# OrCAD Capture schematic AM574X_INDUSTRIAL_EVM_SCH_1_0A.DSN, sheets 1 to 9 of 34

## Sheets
1 Pg09: DDR3 Memory 2: size C; title: TITLE; rev: A; company: Texas Instruments; note: Proj PROC053 001 OPN# TMDSIDK574; note: Catalog Processors BU; note: Final
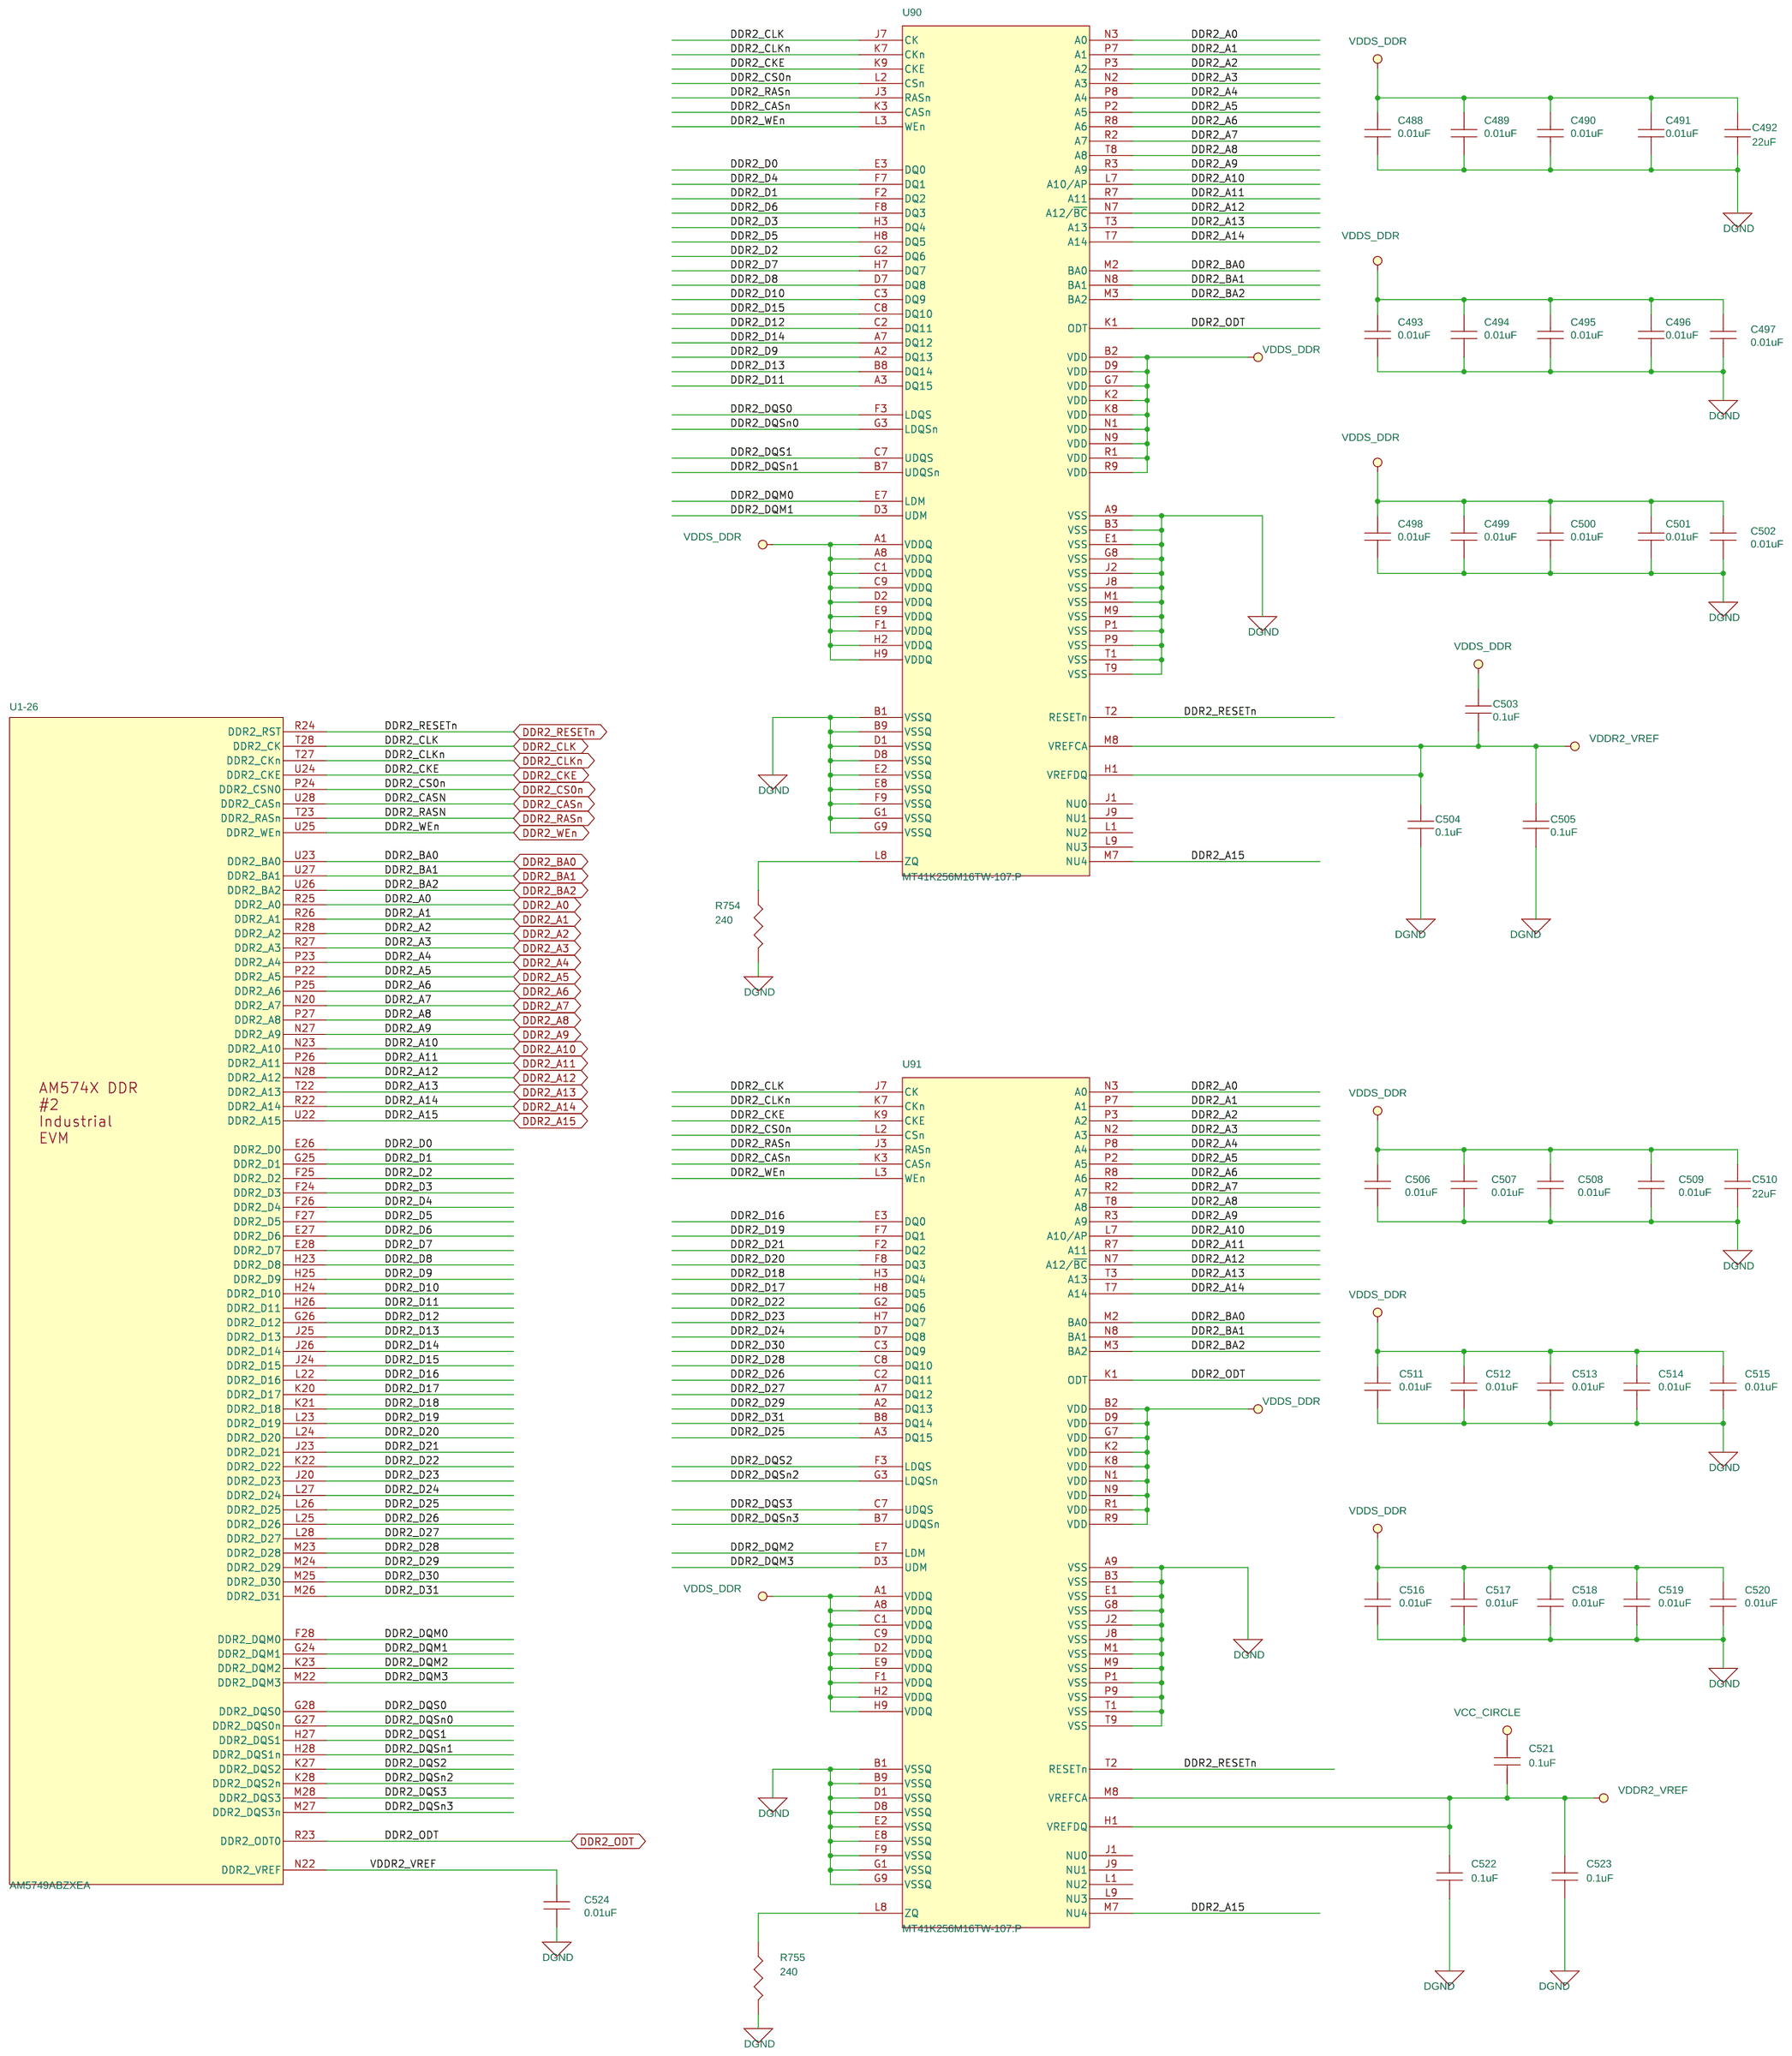
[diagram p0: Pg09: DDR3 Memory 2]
2 Pg24: USB JTAG: size C
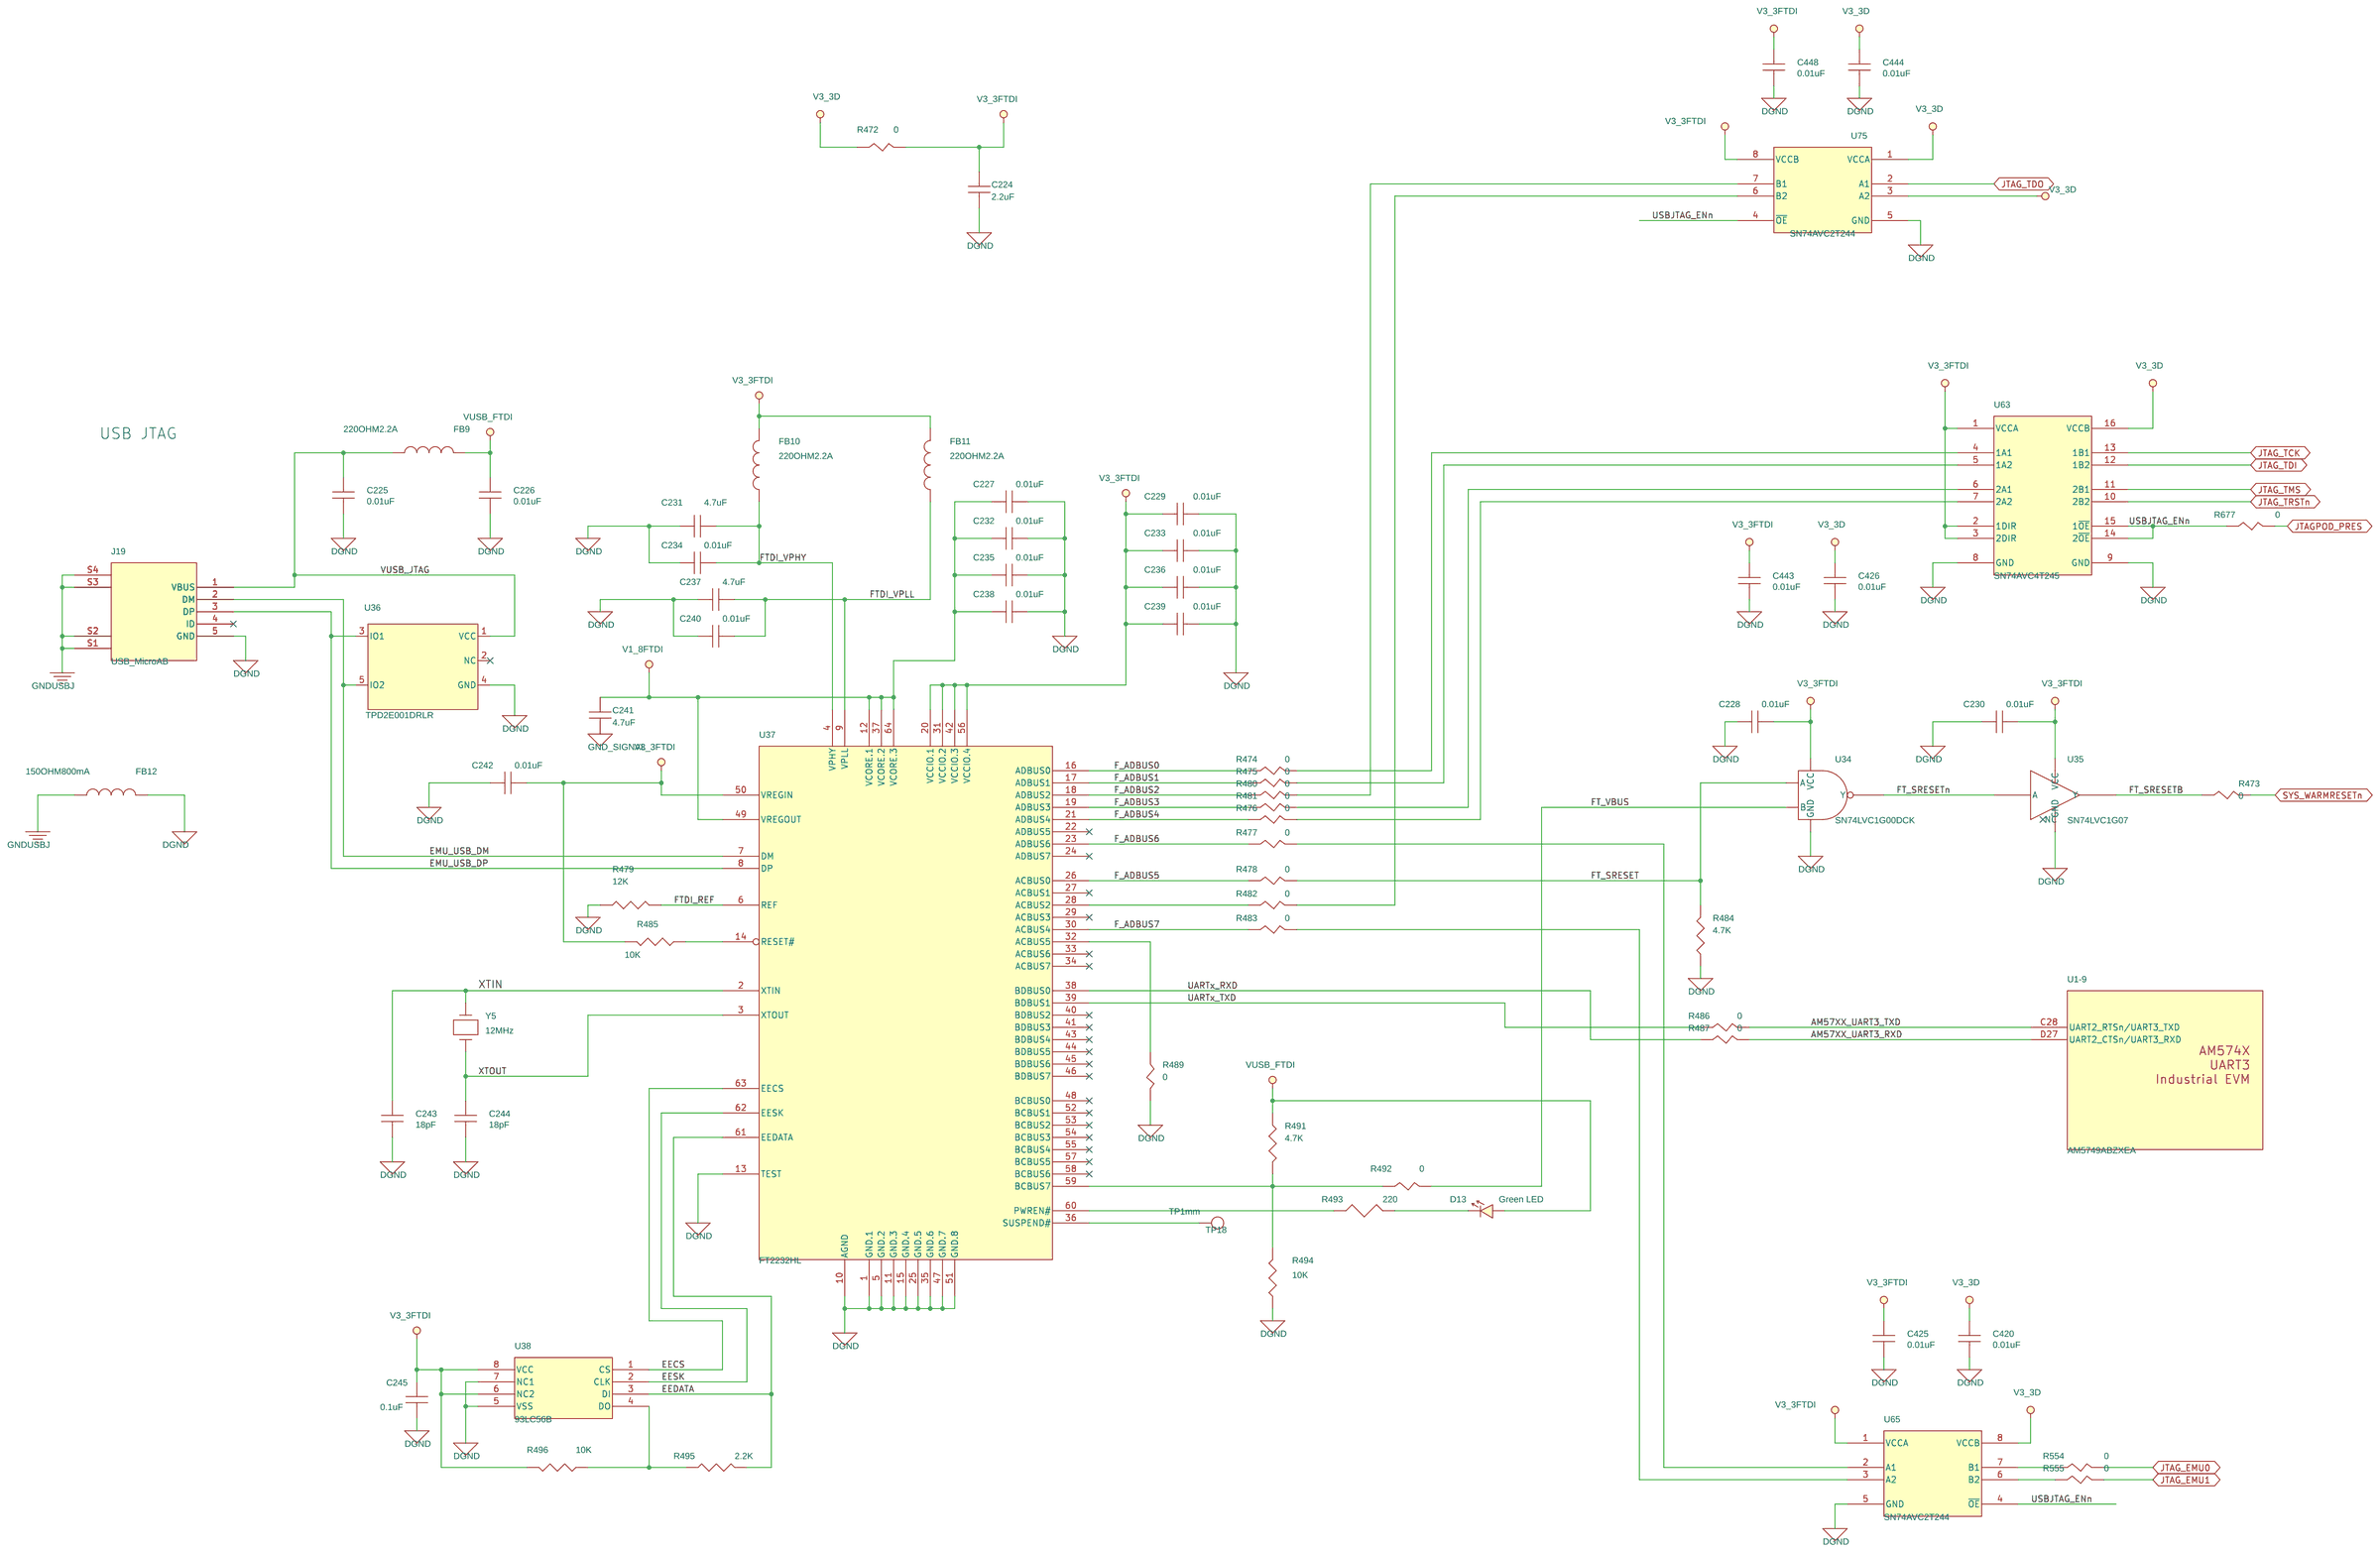
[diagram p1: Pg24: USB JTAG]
3 Pg30: RS-485: size C
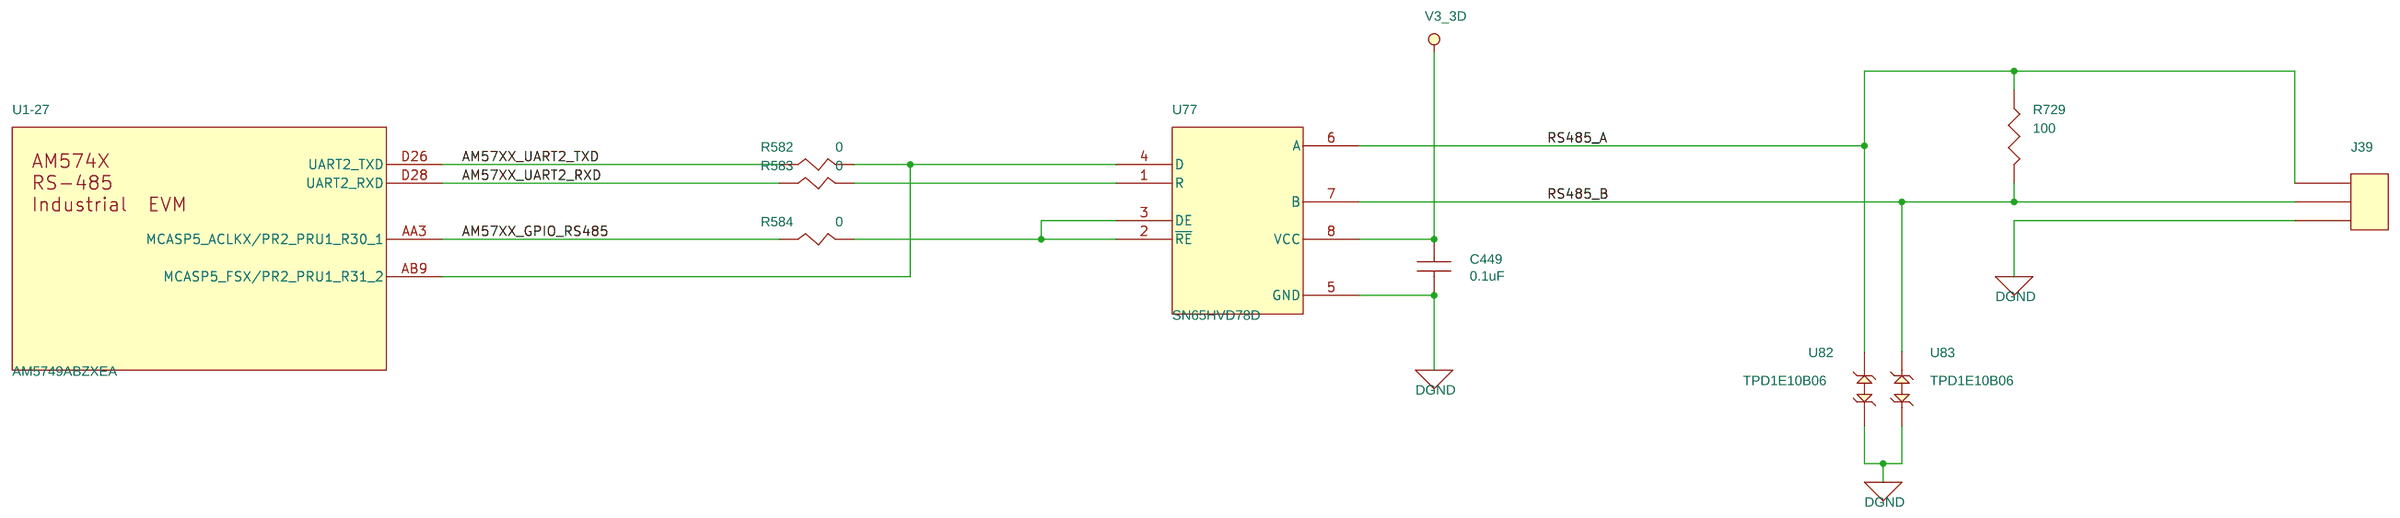
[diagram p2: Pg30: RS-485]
4 Pg22: HDMI: size C
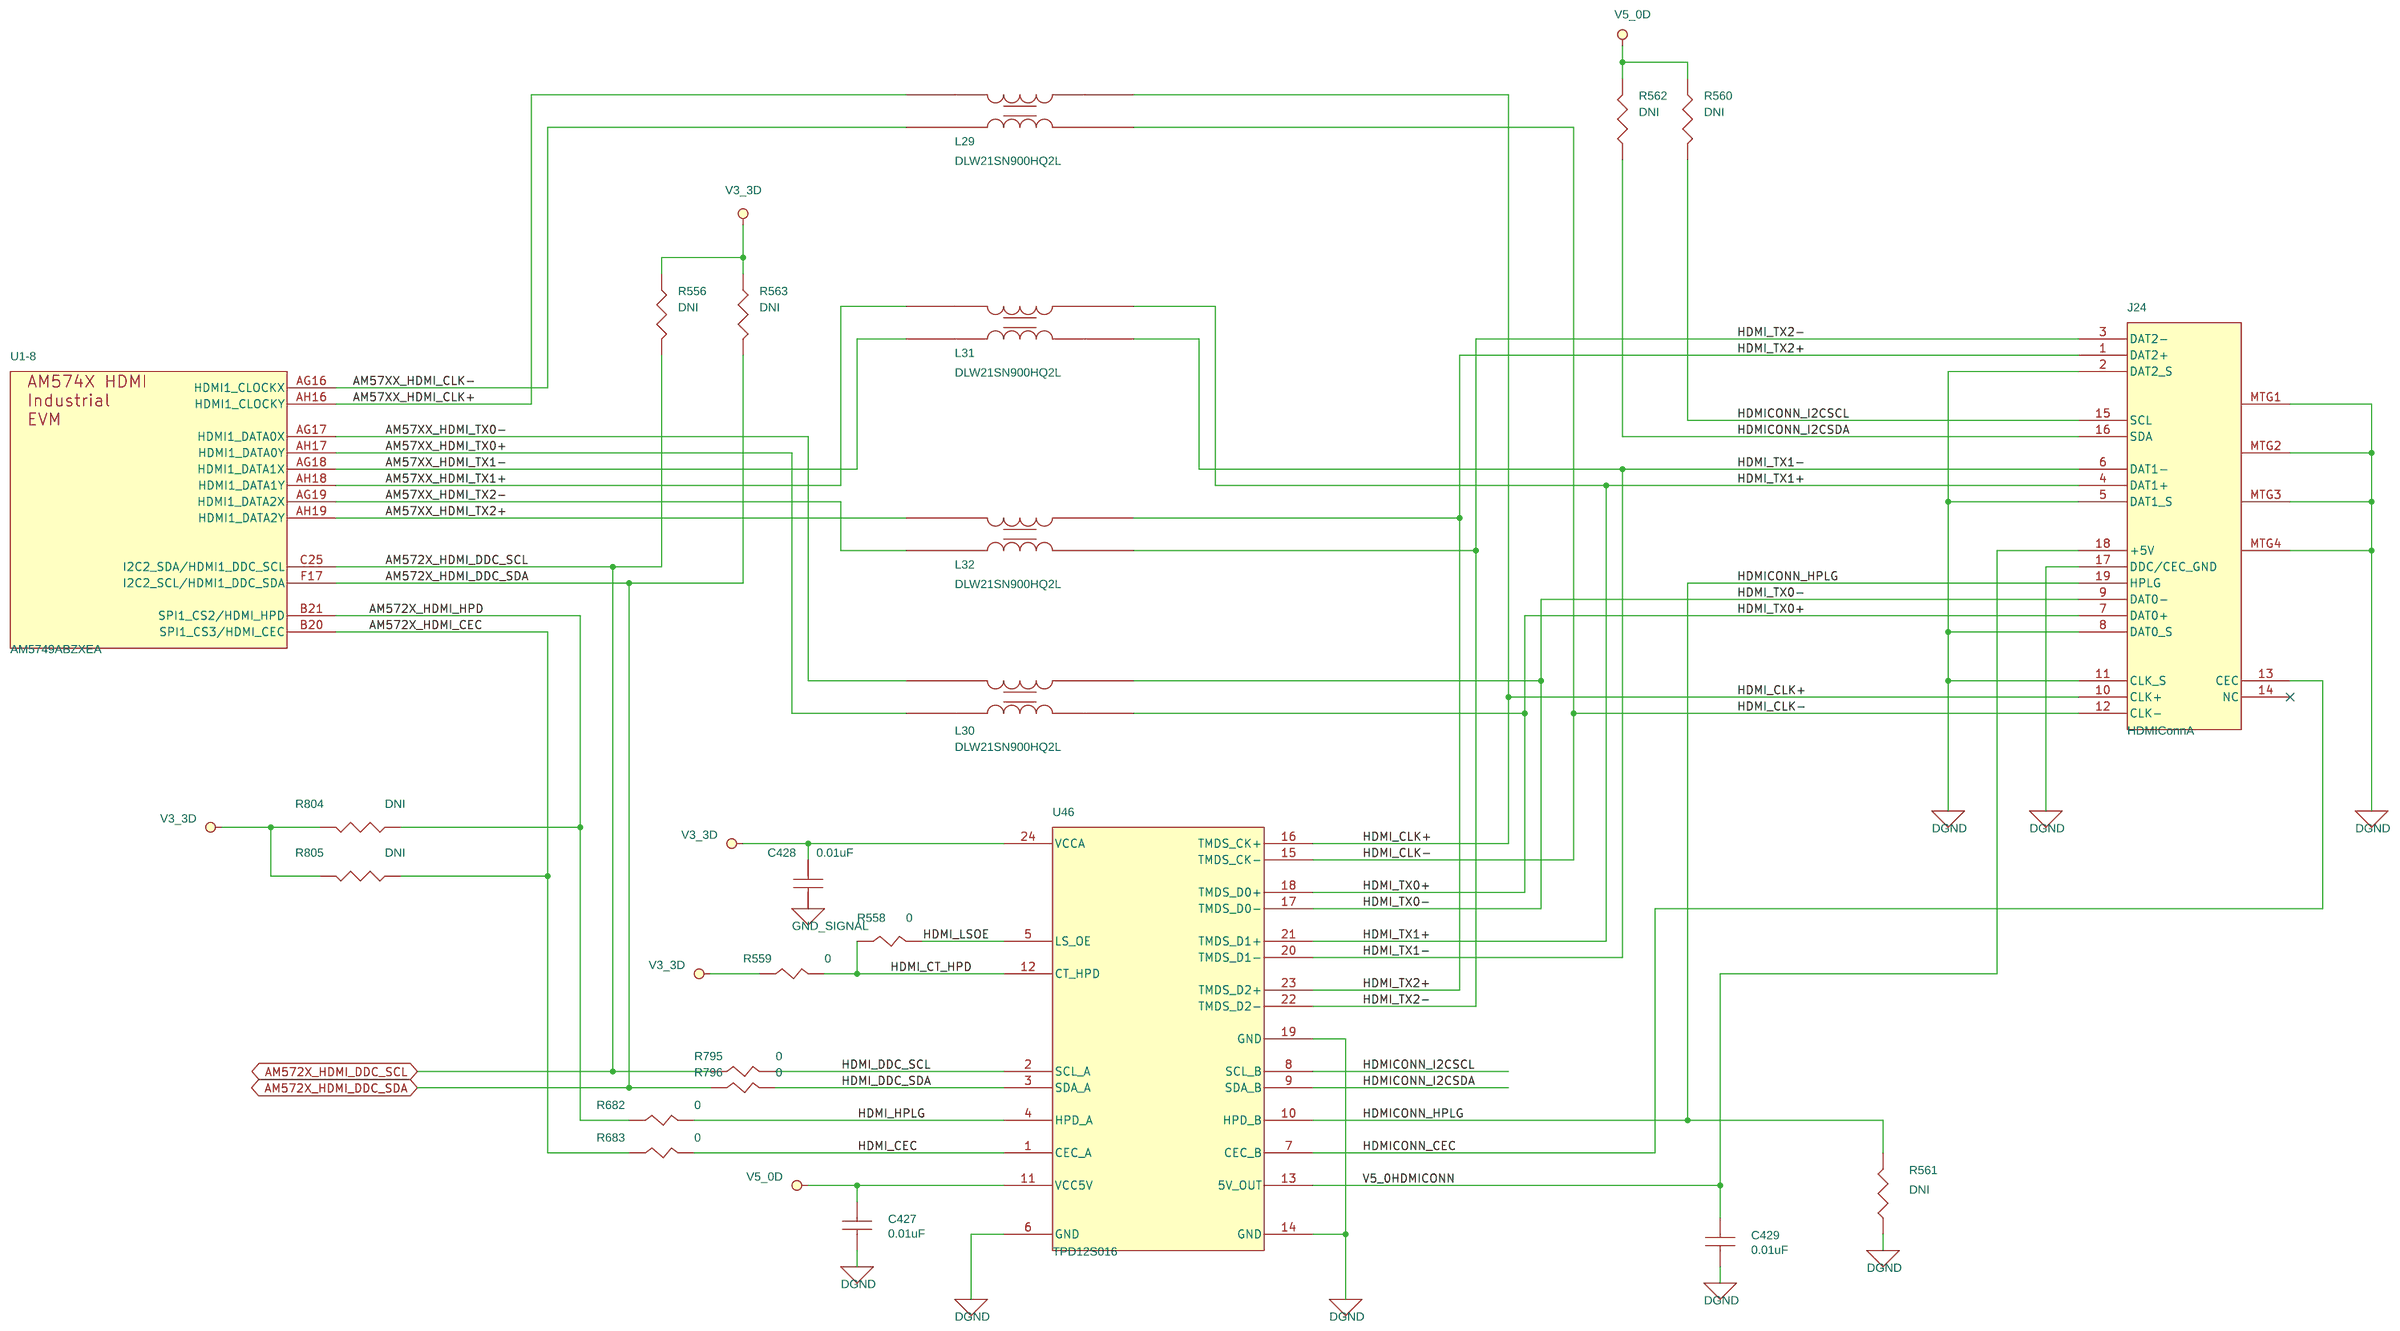
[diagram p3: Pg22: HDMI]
5 Pg21: LCD: size C
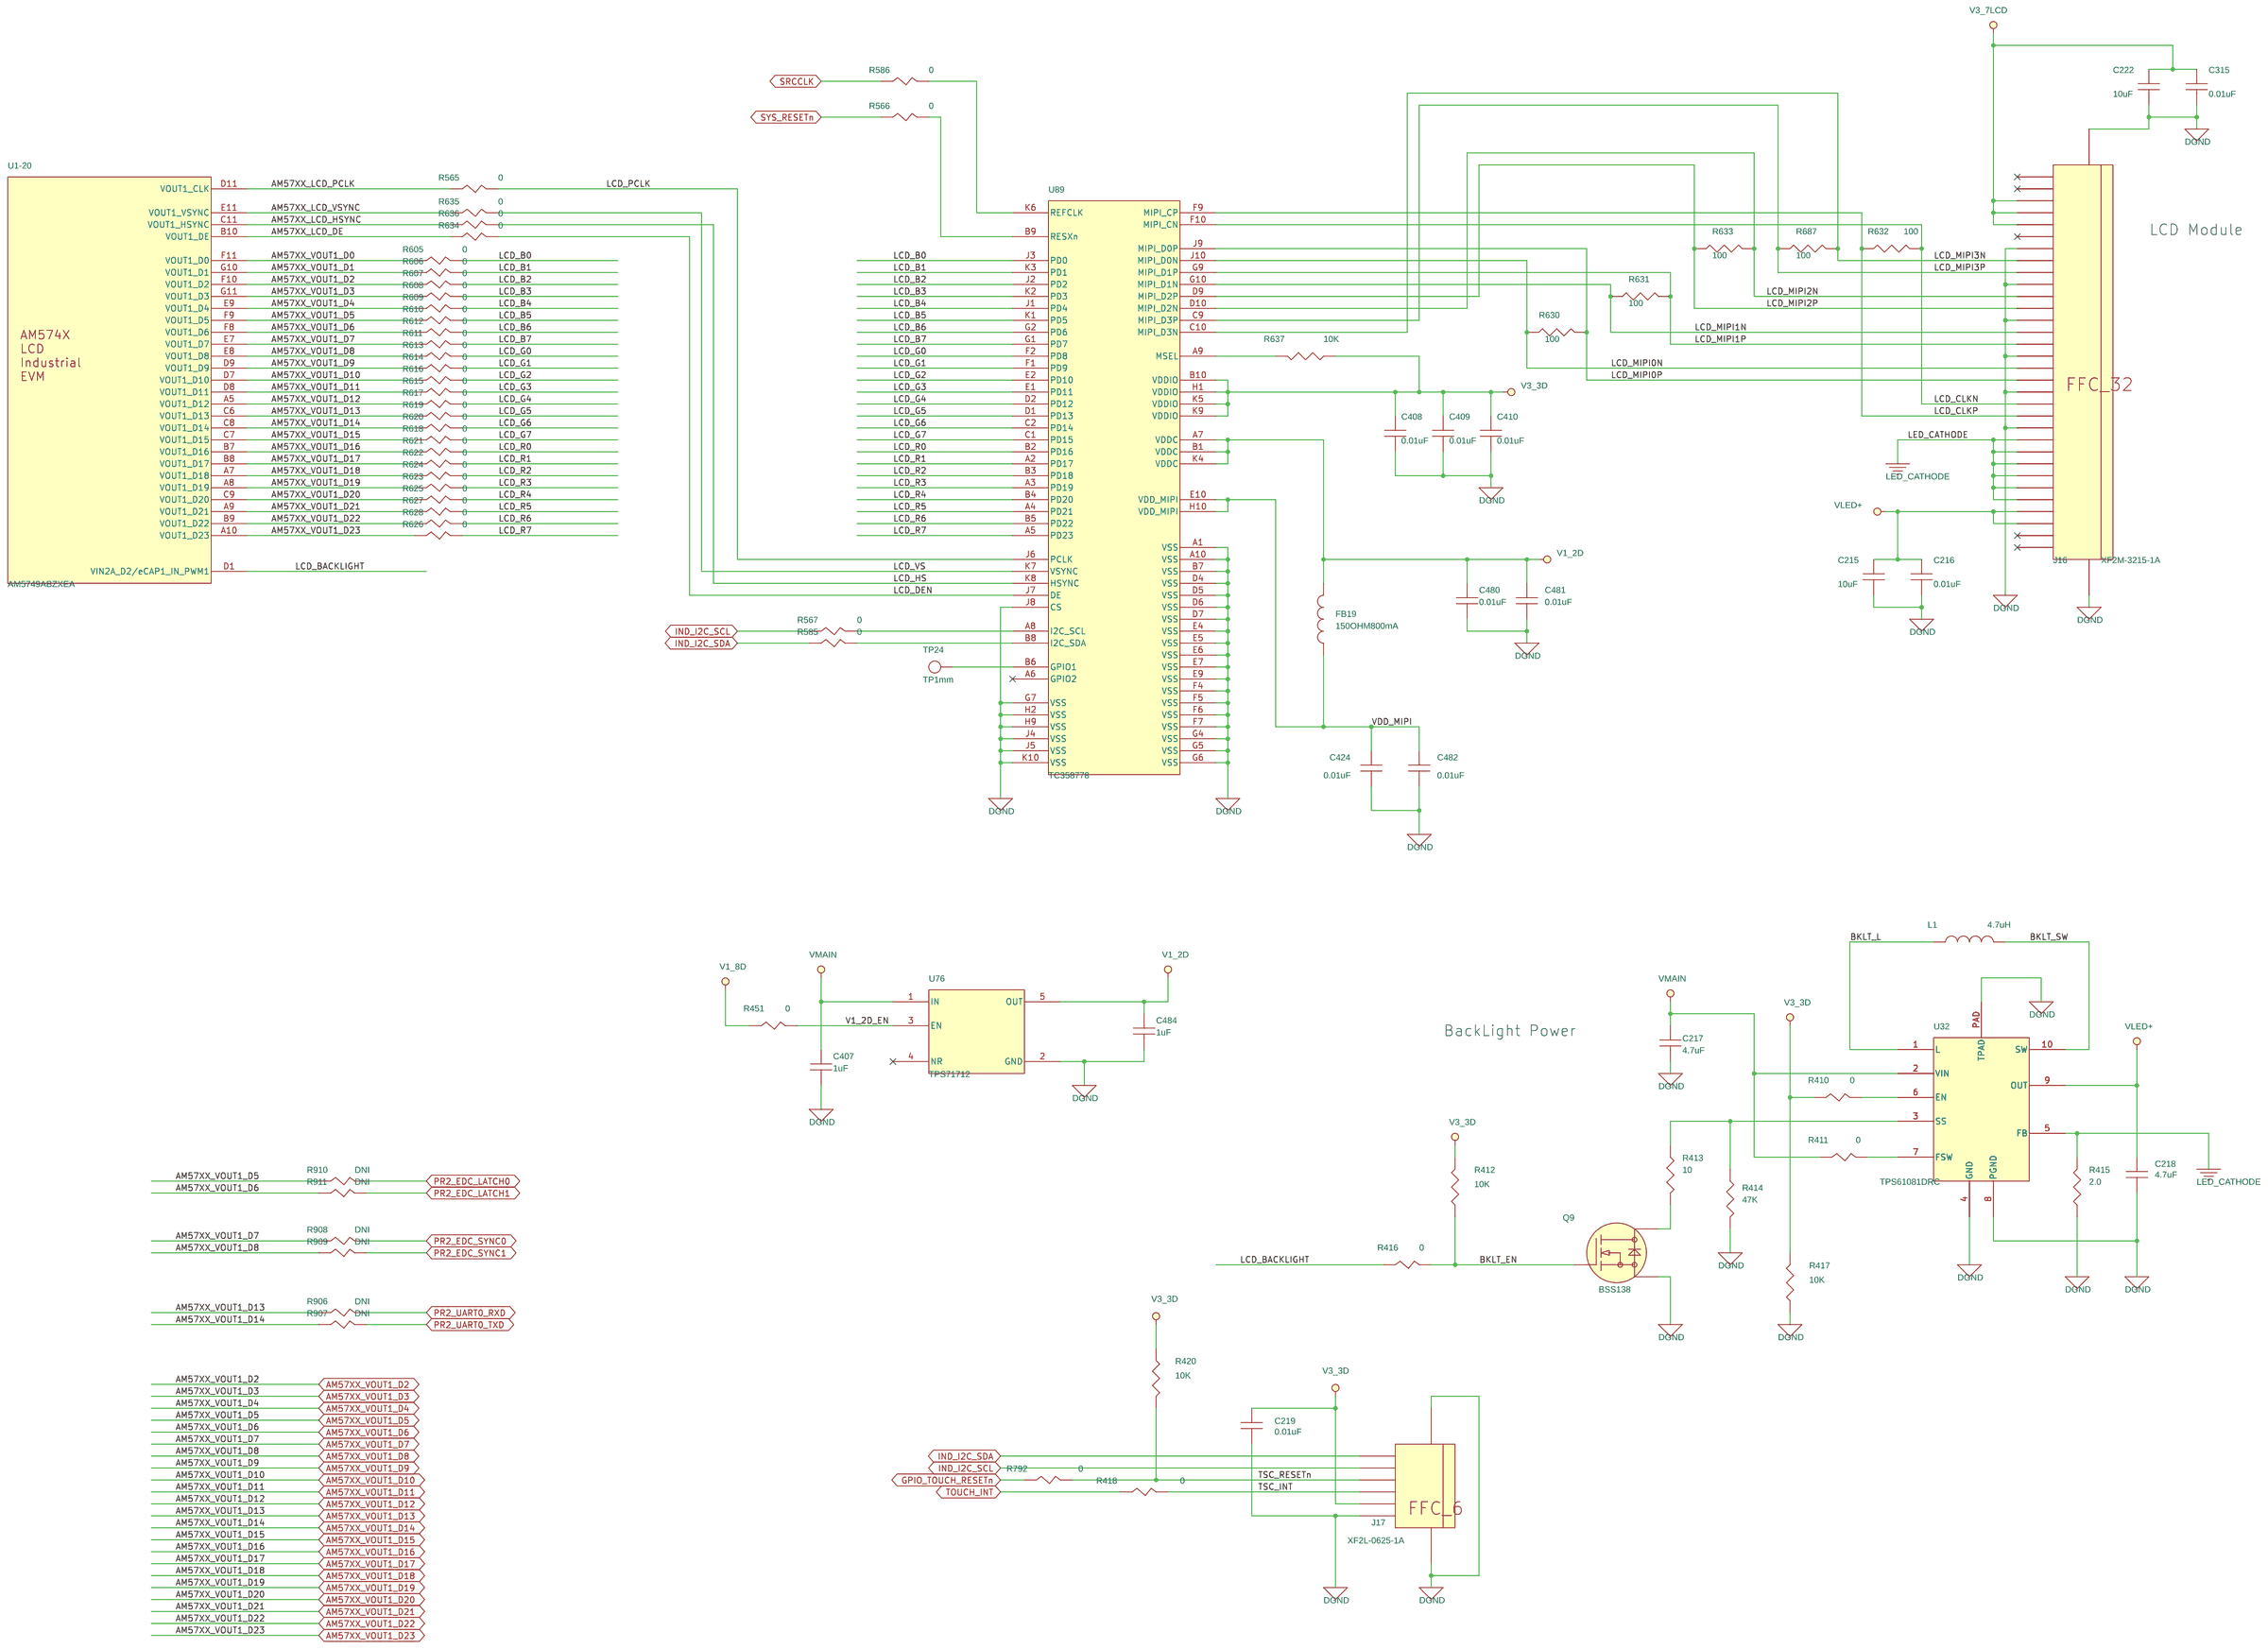
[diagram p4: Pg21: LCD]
6 Pg25: eMMC: size C
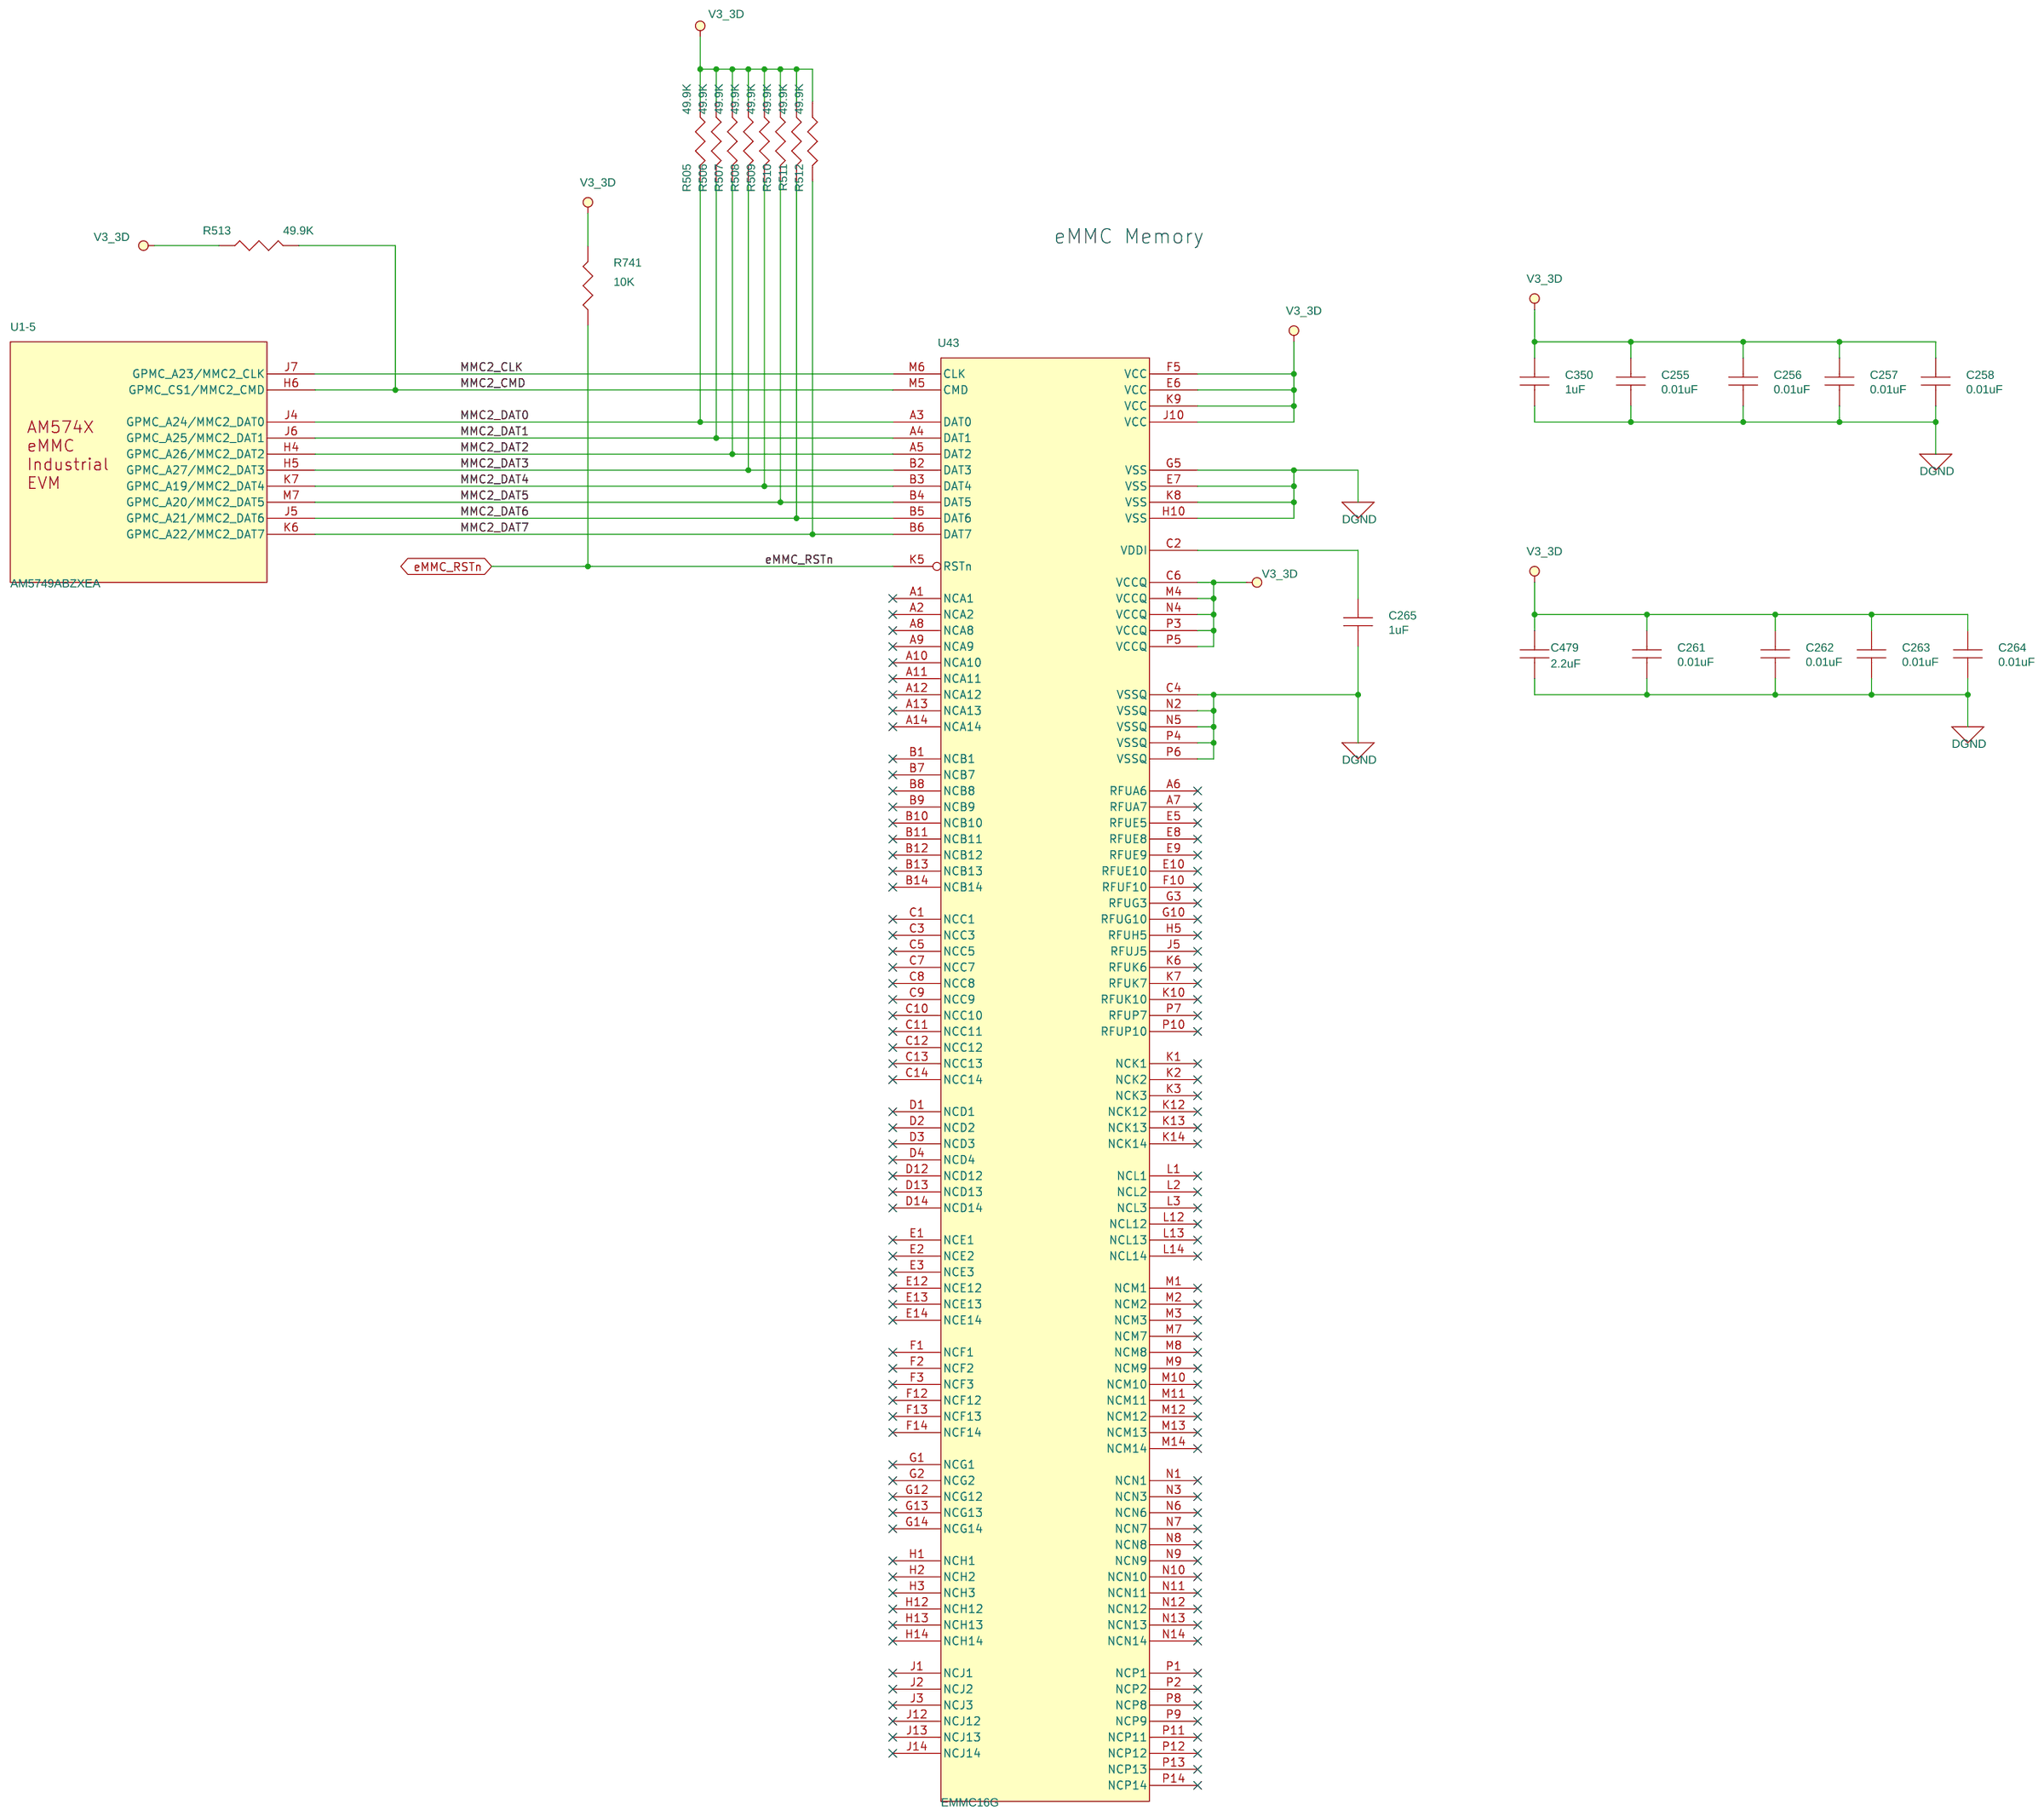
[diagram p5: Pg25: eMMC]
7 Pg34:Hardware
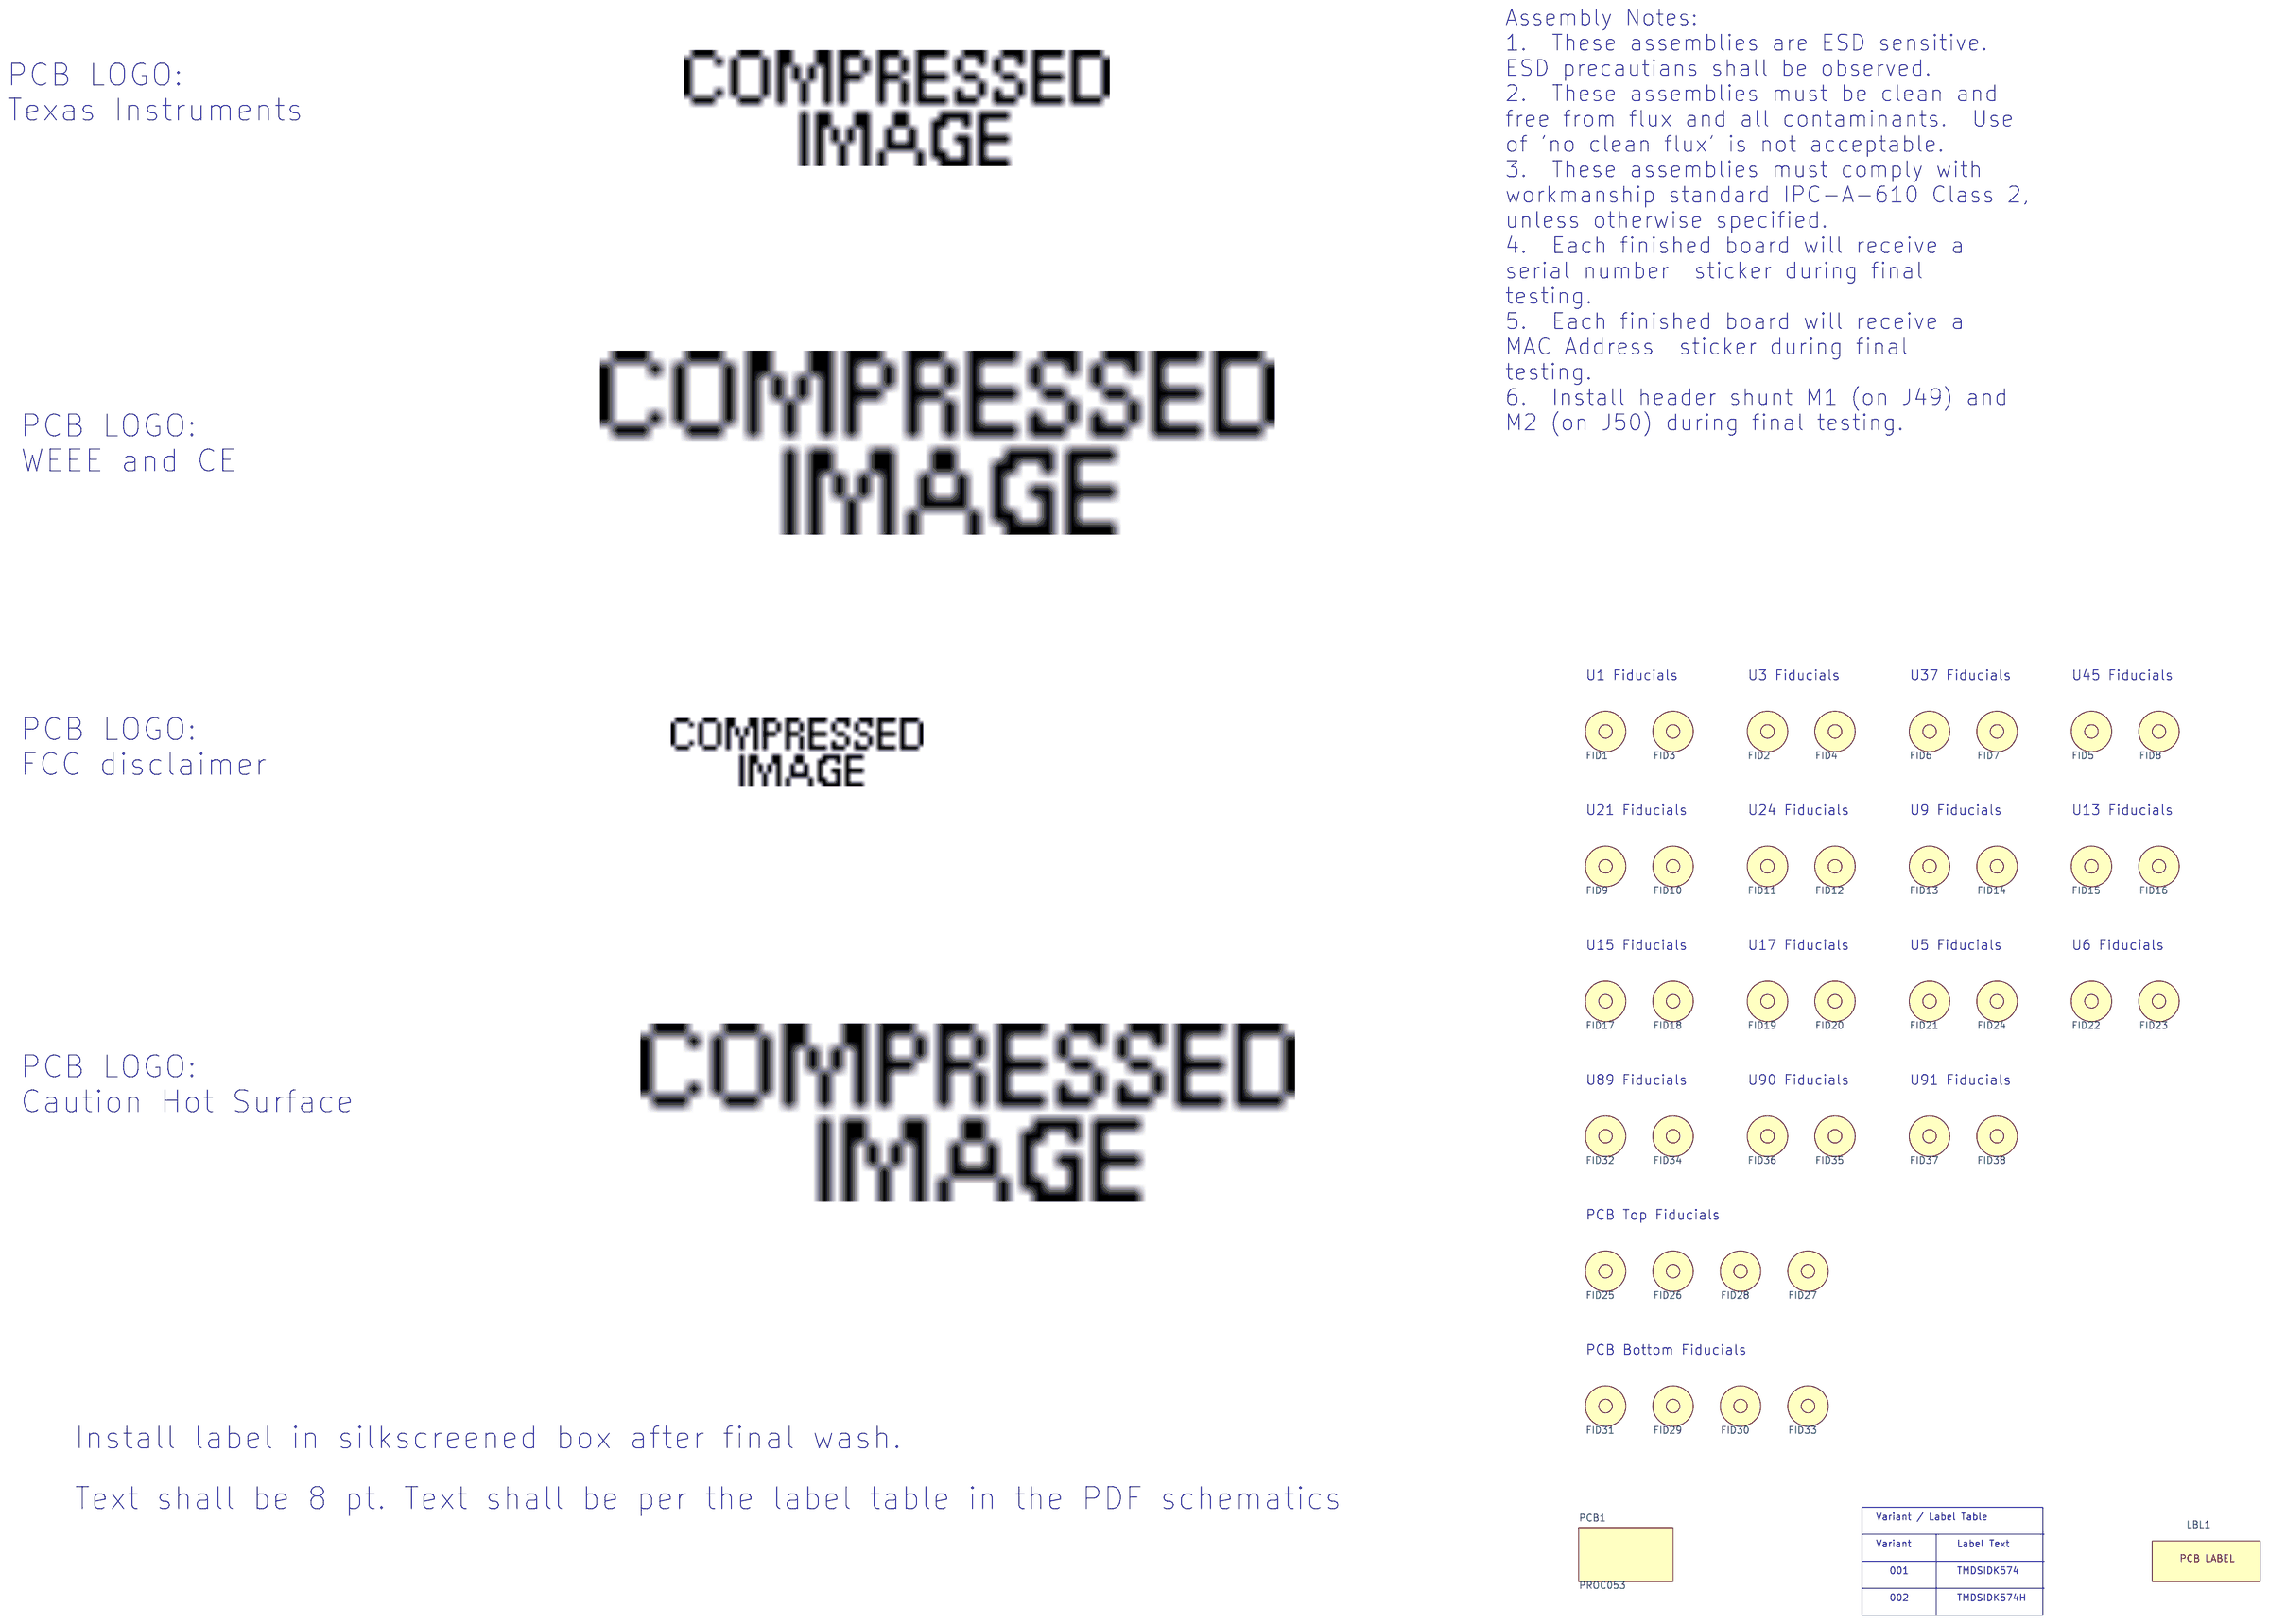
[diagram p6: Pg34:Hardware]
8 Pg28: DCAN #1: size C
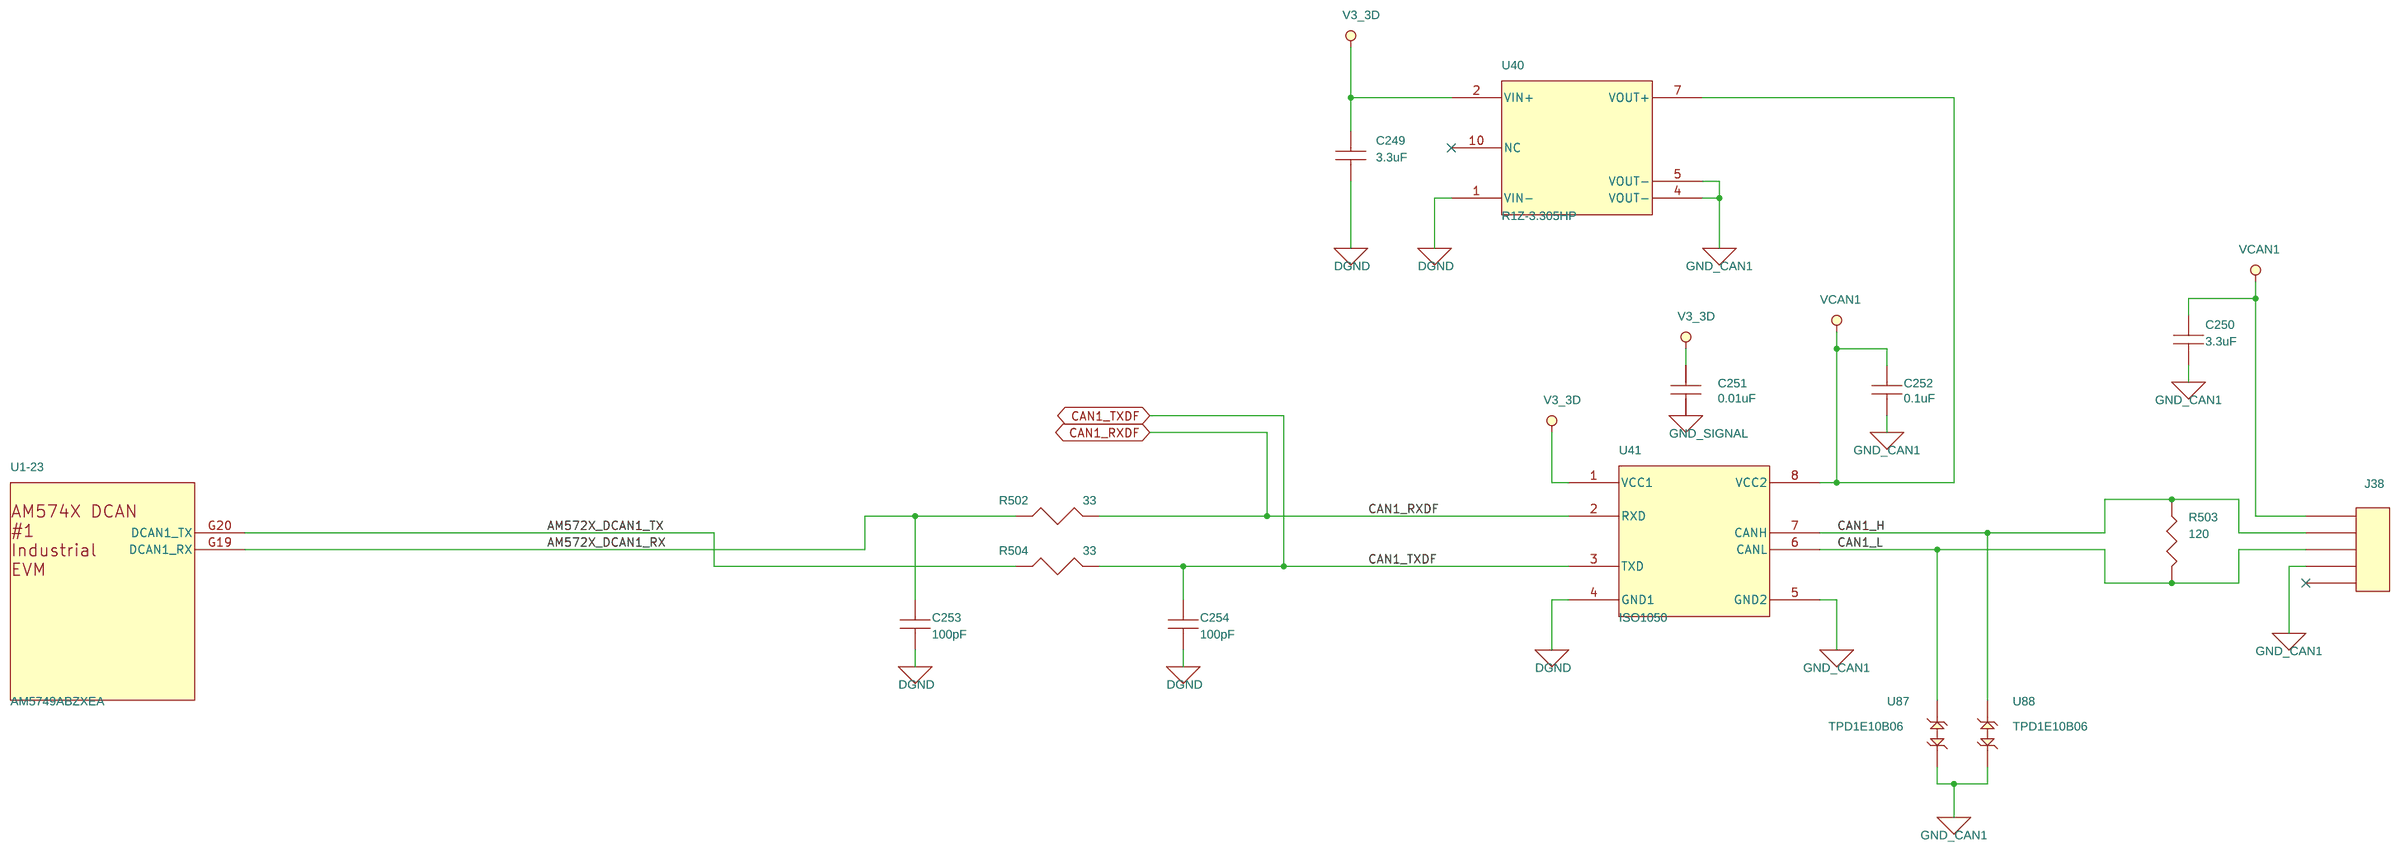
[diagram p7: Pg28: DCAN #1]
9 Pg10: DDR3 VTT: size C
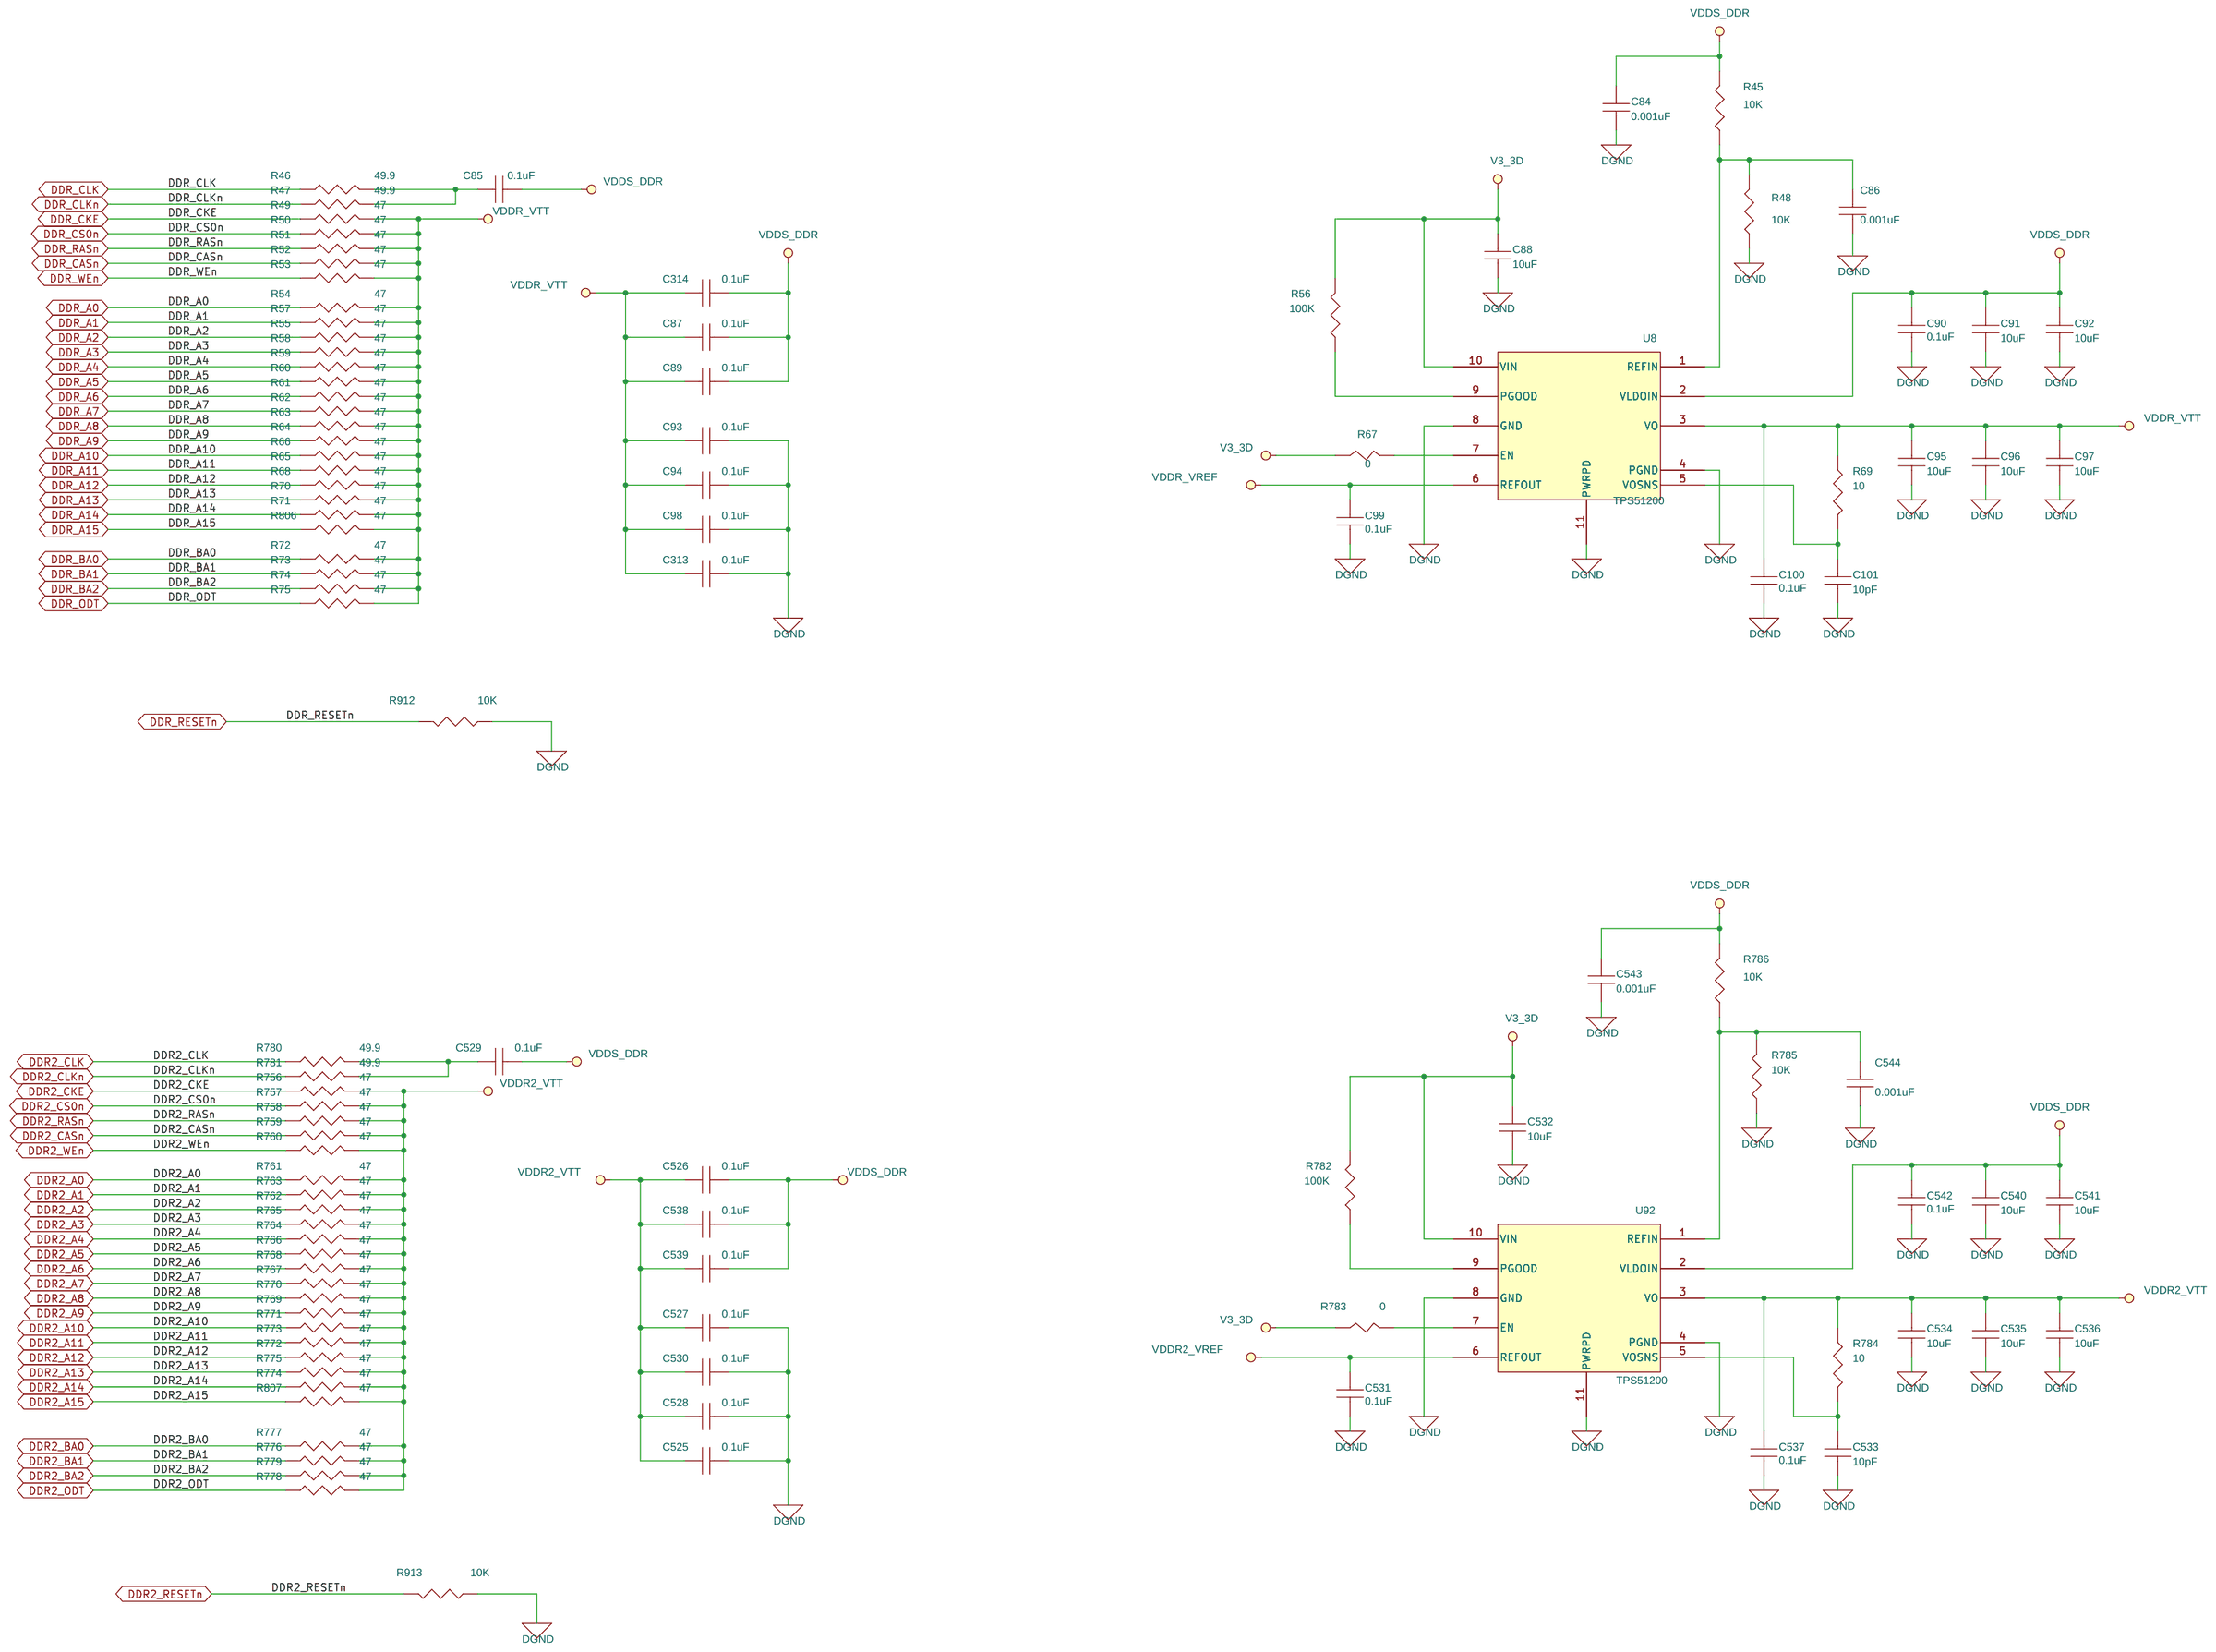
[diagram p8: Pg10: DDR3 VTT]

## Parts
sheet Pg09: DDR3 Memory 2
C488  0.01uF  [SM-7351-CAP-0402]
C489  0.01uF  [SM-7351-CAP-0402]
C490  0.01uF  [SM-7351-CAP-0402]
C491  0.01uF  [SM-7351-CAP-0402]
C492  22uF  [SM-7351-CAP-0805]
C493  0.01uF  [SM-7351-CAP-0402]
C494  0.01uF  [SM-7351-CAP-0402]
C495  0.01uF  [SM-7351-CAP-0402]
C496  0.01uF  [SM-7351-CAP-0402]
C497  0.01uF  [SM-7351-CAP-0402]
C498  0.01uF  [SM-7351-CAP-0402]
C499  0.01uF  [SM-7351-CAP-0402]
C500  0.01uF  [SM-7351-CAP-0402]
C501  0.01uF  [SM-7351-CAP-0402]
C502  0.01uF  [SM-7351-CAP-0402]
C503  0.1uF  [SM-7351-CAP-0402]
C504  0.1uF  [SM-7351-CAP-0402]
C505  0.1uF  [SM-7351-CAP-0402]
C506  0.01uF  [SM-7351-CAP-0402]
C507  0.01uF  [SM-7351-CAP-0402]
C508  0.01uF  [SM-7351-CAP-0402]
C509  0.01uF  [SM-7351-CAP-0402]
C510  22uF  [SM-7351-CAP-0805]
C511  0.01uF  [SM-7351-CAP-0402]
C512  0.01uF  [SM-7351-CAP-0402]
C513  0.01uF  [SM-7351-CAP-0402]
C514  0.01uF  [SM-7351-CAP-0402]
C515  0.01uF  [SM-7351-CAP-0402]
C516  0.01uF  [SM-7351-CAP-0402]
C517  0.01uF  [SM-7351-CAP-0402]
C518  0.01uF  [SM-7351-CAP-0402]
C519  0.01uF  [SM-7351-CAP-0402]
C520  0.01uF  [SM-7351-CAP-0402]
C521  0.1uF  [SM-7351-CAP-0402]
C522  0.1uF  [SM-7351-CAP-0402]
C523  0.1uF  [SM-7351-CAP-0402]
C524  0.01uF  [SM-7351-CAP-0402]
R754  240  [sm-7351-res-0402]
R755  240  [sm-7351-res-0402]
U90  MT41K256M16TW-107:P  [bga9x14-96]
U91  MT41K256M16TW-107:P  [bga9x14-96]
sheet Pg10: DDR3 VTT
C84  0.001uF  [SM-7351-CAP-0402]
C85  0.1uF  [SM-7351-CAP-0402]
C86  0.001uF  [SM-7351-CAP-0402]
C87  0.1uF  [SM-7351-CAP-0402]
C88  10uF  [SM-7351-CAP-0805]
C89  0.1uF  [SM-7351-CAP-0402]
C90  0.1uF  [SM-7351-CAP-0402]
C91  10uF  [SM-7351-CAP-0805]
C92  10uF  [SM-7351-CAP-0805]
C93  0.1uF  [SM-7351-CAP-0402]
C94  0.1uF  [SM-7351-CAP-0402]
C95  10uF  [SM-7351-CAP-0805]
C96  10uF  [SM-7351-CAP-0805]
C97  10uF  [SM-7351-CAP-0805]
C98  0.1uF  [SM-7351-CAP-0402]
C99  0.1uF  [SM-7351-CAP-0402]
C100  0.1uF  [SM-7351-CAP-0402]
C101  10pF  [SM-7351-CAP-0402]
C313  0.1uF  [SM-7351-CAP-0402]
C314  0.1uF  [SM-7351-CAP-0402]
C525  0.1uF  [SM-7351-CAP-0402]
C526  0.1uF  [SM-7351-CAP-0402]
C527  0.1uF  [SM-7351-CAP-0402]
C528  0.1uF  [SM-7351-CAP-0402]
C529  0.1uF  [SM-7351-CAP-0402]
C530  0.1uF  [SM-7351-CAP-0402]
C531  0.1uF  [SM-7351-CAP-0402]
C532  10uF  [SM-7351-CAP-0805]
C533  10pF  [SM-7351-CAP-0402]
C534  10uF  [SM-7351-CAP-0805]
C535  10uF  [SM-7351-CAP-0805]
C536  10uF  [SM-7351-CAP-0805]
C537  0.1uF  [SM-7351-CAP-0402]
C538  0.1uF  [SM-7351-CAP-0402]
C539  0.1uF  [SM-7351-CAP-0402]
C540  10uF  [SM-7351-CAP-0805]
C541  10uF  [SM-7351-CAP-0805]
C542  0.1uF  [SM-7351-CAP-0402]
C543  0.001uF  [SM-7351-CAP-0402]
C544  0.001uF  [SM-7351-CAP-0402]
R45  10K  [SM-7351-RES-0402]
R46  49.9  [SM-7351-RES-0402]
R47  49.9  [SM-7351-RES-0402]
R48  10K  [SM-7351-RES-0402]
R49  47  [SM-7351-RES-0402]
R50  47  [SM-7351-RES-0402]
R51  47  [SM-7351-RES-0402]
R52  47  [SM-7351-RES-0402]
R53  47  [SM-7351-RES-0402]
R54  47  [SM-7351-RES-0402]
R55  47  [SM-7351-RES-0402]
R56  100K  [SM-7351-RES-0402]
R57  47  [SM-7351-RES-0402]
R58  47  [SM-7351-RES-0402]
R59  47  [SM-7351-RES-0402]
R60  47  [SM-7351-RES-0402]
R61  47  [SM-7351-RES-0402]
R62  47  [SM-7351-RES-0402]
R63  47  [SM-7351-RES-0402]
R64  47  [SM-7351-RES-0402]
R65  47  [SM-7351-RES-0402]
R66  47  [SM-7351-RES-0402]
R67  0  [SM-7351-RES-0402]
R68  47  [SM-7351-RES-0402]
R69  10  [SM-7351-RES-0402]
R70  47  [SM-7351-RES-0402]
R71  47  [SM-7351-RES-0402]
R72  47  [SM-7351-RES-0402]
R73  47  [SM-7351-RES-0402]
R74  47  [SM-7351-RES-0402]
R75  47  [SM-7351-RES-0402]
R756  47  [SM-7351-RES-0402]
R757  47  [SM-7351-RES-0402]
R758  47  [SM-7351-RES-0402]
R759  47  [SM-7351-RES-0402]
R760  47  [SM-7351-RES-0402]
R761  47  [SM-7351-RES-0402]
R762  47  [SM-7351-RES-0402]
R763  47  [SM-7351-RES-0402]
R764  47  [SM-7351-RES-0402]
R765  47  [SM-7351-RES-0402]
R766  47  [SM-7351-RES-0402]
R767  47  [SM-7351-RES-0402]
R768  47  [SM-7351-RES-0402]
R769  47  [SM-7351-RES-0402]
R770  47  [SM-7351-RES-0402]
R771  47  [SM-7351-RES-0402]
R772  47  [SM-7351-RES-0402]
R773  47  [SM-7351-RES-0402]
R774  47  [SM-7351-RES-0402]
R775  47  [SM-7351-RES-0402]
R776  47  [SM-7351-RES-0402]
R777  47  [SM-7351-RES-0402]
R778  47  [SM-7351-RES-0402]
R779  47  [SM-7351-RES-0402]
R780  49.9  [SM-7351-RES-0402]
R781  49.9  [SM-7351-RES-0402]
R782  100K  [SM-7351-RES-0402]
R783  0  [SM-7351-RES-0402]
R784  10  [SM-7351-RES-0402]
R785  10K  [SM-7351-RES-0402]
R786  10K  [SM-7351-RES-0402]
R806  47  [SM-7351-RES-0402]
R807  47  [SM-7351-RES-0402]
R912  10K  [SM-7351-RES-0402]
R913  10K  [SM-7351-RES-0402]
U8  TPS51200  [drcpso_10pin]
U92  TPS51200  [drcpso_10pin]
sheet Pg21: LCD
C215  10uF  [SM-7351-CAP-0805]
C216  0.01uF  [SM-7351-CAP-0402]
C217  4.7uF  [SM-7351-CAP-0603]
C218  4.7uF  [SM-7351-CAP-0805]
C219  0.01uF  [SM-7351-CAP-0402]
C222  10uF  [SM-7351-CAP-0805]
C315  0.01uF  [SM-7351-CAP-0402]
C407  1uF  [SM-7351-CAP-0402]
C408  0.01uF  [SM-7351-CAP-0402]
C409  0.01uF  [SM-7351-CAP-0402]
C410  0.01uF  [SM-7351-CAP-0402]
C424  0.01uF  [SM-7351-CAP-0402]
C480  0.01uF  [SM-7351-CAP-0402]
C481  0.01uF  [SM-7351-CAP-0402]
C482  0.01uF  [SM-7351-CAP-0402]
C484  1uF  [SM-7351-CAP-0402]
FB19  150OHM800mA  [sm-7351-ind-0805]
J16  XF2M-3215-1A  [CNXF2M-3215-1A]
J17  XF2L-0625-1A  [CNXF2L-0625-1A]
L1  4.7uH  [vlcf5020t]
Q9  BSS138  [SOT23-3]
R410  0  [SM-7351-RES-0402]
R411  0  [SM-7351-RES-0402]
R412  10K  [SM-7351-RES-0402]
R413  10  [SM-7351-RES-0402]
R414  47K  [SM-7351-RES-0402]
R415  2.0  [SM-7351-RES-0603]
R416  0  [SM-7351-RES-0402]
R417  10K  [SM-7351-RES-0402]
R418  0  [SM-7351-RES-0402]
R420  10K  [SM-7351-RES-0402]
R451  0  [SM-7351-RES-0402]
R565  0  [SM-7351-RES-0402]
R566  0  [SM-7351-RES-0402]
R567  0  [SM-7351-RES-0402]
R585  0  [SM-7351-RES-0402]
R586  0  [SM-7351-RES-0402]
R605  0  [SM-7351-RES-0402]
R606  0  [SM-7351-RES-0402]
R607  0  [SM-7351-RES-0402]
R608  0  [SM-7351-RES-0402]
R609  0  [SM-7351-RES-0402]
R610  0  [SM-7351-RES-0402]
R611  0  [SM-7351-RES-0402]
R612  0  [SM-7351-RES-0402]
R613  0  [SM-7351-RES-0402]
R614  0  [SM-7351-RES-0402]
R615  0  [SM-7351-RES-0402]
R616  0  [SM-7351-RES-0402]
R617  0  [SM-7351-RES-0402]
R618  0  [SM-7351-RES-0402]
R619  0  [SM-7351-RES-0402]
R620  0  [SM-7351-RES-0402]
R621  0  [SM-7351-RES-0402]
R622  0  [SM-7351-RES-0402]
R623  0  [SM-7351-RES-0402]
R624  0  [SM-7351-RES-0402]
R625  0  [SM-7351-RES-0402]
R626  0  [SM-7351-RES-0402]
R627  0  [SM-7351-RES-0402]
R628  0  [SM-7351-RES-0402]
R630  100  [SM-7351-RES-0402]
R631  100  [SM-7351-RES-0402]
R632  100  [SM-7351-RES-0402]
R633  100  [SM-7351-RES-0402]
R634  0  [SM-7351-RES-0402]
R635  0  [SM-7351-RES-0402]
R636  0  [SM-7351-RES-0402]
R637  10K  [SM-7351-RES-0402]
R687  100  [SM-7351-RES-0402]
R792  0  [SM-7351-RES-0402]
R906  DNI  [SM-7351-RES-0402]
R907  DNI  [SM-7351-RES-0402]
R908  DNI  [SM-7351-RES-0402]
R909  DNI  [SM-7351-RES-0402]
R910  DNI  [SM-7351-RES-0402]
R911  DNI  [SM-7351-RES-0402]
TP24  TP1mm  [tp_smd1mmcircle]
U32  TPS61081DRC  [u_10_drc]
U76  TPS71712  [smdsc70-5]
U89  TC358778  [BGA7X7-80-39M]
sheet Pg22: HDMI
C427  0.01uF  [SM-7351-CAP-0402]
C428  0.01uF  [SM-7351-CAP-0402]
C429  0.01uF  [SM-7351-CAP-0402]
J24  HDMIConnA  [smd_hdmia_ra]
L29  DLW21SN900HQ2L  [filt-dlw21s]
L30  DLW21SN900HQ2L  [filt-dlw21s]
L31  DLW21SN900HQ2L  [filt-dlw21s]
L32  DLW21SN900HQ2L  [filt-dlw21s]
R556  DNI  [sm-7351-res-0402]
R558  0  [SM-7351-RES-0402]
R559  0  [SM-7351-RES-0402]
R560  DNI  [SM-7351-RES-0402]
R561  DNI  [SM-7351-RES-0402]
R562  DNI  [SM-7351-RES-0402]
R563  DNI  [sm-7351-res-0402]
R682  0  [SM-7351-RES-0402]
R683  0  [SM-7351-RES-0402]
R795  0  [SM-7351-RES-0402]
R796  0  [SM-7351-RES-0402]
R804  DNI  [SM-7351-RES-0402]
R805  DNI  [SM-7351-RES-0402]
U46  TPD12S016  [pw_24pin_tssop]
sheet Pg24: USB JTAG
C224  2.2uF  [SM-7351-CAP-0805]
C225  0.01uF  [SM-7351-CAP-0402]
C226  0.01uF  [SM-7351-CAP-0402]
C227  0.01uF  [SM-7351-CAP-0402]
C228  0.01uF  [SM-7351-CAP-0402]
C229  0.01uF  [SM-7351-CAP-0402]
C230  0.01uF  [SM-7351-CAP-0402]
C231  4.7uF  [SM-7351-CAP-0603]
C232  0.01uF  [SM-7351-CAP-0402]
C233  0.01uF  [SM-7351-CAP-0402]
C234  0.01uF  [SM-7351-CAP-0402]
C235  0.01uF  [SM-7351-CAP-0402]
C236  0.01uF  [SM-7351-CAP-0402]
C237  4.7uF  [SM-7351-CAP-0603]
C238  0.01uF  [SM-7351-CAP-0402]
C239  0.01uF  [SM-7351-CAP-0402]
C240  0.01uF  [SM-7351-CAP-0402]
C241  4.7uF  [SM-7351-CAP-0603]
C242  0.01uF  [SM-7351-CAP-0402]
C243  18pF  [SM-7351-CAP-0402]
C244  18pF  [SM-7351-CAP-0402]
C245  0.1uF  [SM-7351-CAP-0402]
C420  0.01uF  [SM-7351-CAP-0402]
C425  0.01uF  [SM-7351-CAP-0402]
C426  0.01uF  [SM-7351-CAP-0402]
C443  0.01uF  [SM-7351-CAP-0402]
C444  0.01uF  [SM-7351-CAP-0402]
C448  0.01uF  [SM-7351-CAP-0402]
D13  Green LED  [sm_led_0805]
FB9  220OHM2.2A  [sm-7351-ind-0603]
FB10  220OHM2.2A  [sm-7351-ind-0603]
FB11  220OHM2.2A  [sm-7351-ind-0603]
FB12  150OHM800mA  [sm-7351-ind-0805]
J19  USB_MicroAB  [ZX62-AB-5PA]
R472  0  [SM-7351-RES-0603]
R473  0  [SM-7351-RES-0402]
R474  0  [SM-7351-RES-0402]
R475  0  [SM-7351-RES-0402]
R476  0  [SM-7351-RES-0402]
R477  0  [SM-7351-RES-0402]
R478  0  [SM-7351-RES-0402]
R479  12K  [SM-7351-RES-0402]
R480  0  [SM-7351-RES-0402]
R481  0  [SM-7351-RES-0402]
R482  0  [SM-7351-RES-0402]
R483  0  [SM-7351-RES-0402]
R484  4.7K  [SM-7351-RES-0402]
R485  10K  [SM-7351-RES-0402]
R486  0  [SM-7351-RES-0402]
R487  0  [SM-7351-RES-0402]
R489  0  [SM-7351-RES-0402]
R491  4.7K  [SM-7351-RES-0402]
R492  0  [SM-7351-RES-0402]
R493  220  [SM-7351-RES-0402]
R494  10K  [SM-7351-RES-0402]
R495  2.2K  [sm-7351-res-0402]
R496  10K  [SM-7351-RES-0402]
R554  0  [SM-7351-RES-0402]
R555  0  [SM-7351-RES-0402]
R677  0  [SM-7351-RES-0402]
TP18  TP1mm  [tp_smd1mmcircle]
U34  SN74LVC1G00DCK  [U_5_DCK]
U35  SN74LVC1G07  [u_5_dck]
U36  TPD2E001DRLR  [U_5_DRL]
U37  FT2232HL  [LQFP64pin]
U38  93LC56B  [SOIC_8]
U63  SN74AVC4T245  [U_16_PW]
U65  SN74AVC2T244  [son2x1-8-16m]
U75  SN74AVC2T244  [son2x1-8-16m]
Y5  12MHz  [SM_OSC_ABM3]
sheet Pg25: eMMC
C255  0.01uF  [SM-7351-CAP-0402]
C256  0.01uF  [SM-7351-CAP-0402]
C257  0.01uF  [SM-7351-CAP-0402]
C258  0.01uF  [SM-7351-CAP-0402]
C261  0.01uF  [SM-7351-CAP-0402]
C262  0.01uF  [SM-7351-CAP-0402]
C263  0.01uF  [SM-7351-CAP-0402]
C264  0.01uF  [SM-7351-CAP-0402]
C265  1uF  [SM-7351-CAP-0402]
C350  1uF  [SM-7351-CAP-0402]
C479  2.2uF  [SM-7351-CAP-0805]
R505  49.9K  [SM-7351-RES-0402]
R506  49.9K  [SM-7351-RES-0402]
R507  49.9K  [SM-7351-RES-0402]
R508  49.9K  [SM-7351-RES-0402]
R509  49.9K  [SM-7351-RES-0402]
R510  49.9K  [SM-7351-RES-0402]
R511  49.9K  [SM-7351-RES-0402]
R512  49.9K  [SM-7351-RES-0402]
R513  49.9K  [SM-7351-RES-0402]
R741  10K  [SM-7351-RES-0402]
U43  EMMC16G  [BGA11X13-153-39M]
sheet Pg28: DCAN #1
C249  3.3uF  [SM-7351-CAP-0603]
C250  3.3uF  [SM-7351-CAP-0603]
C251  0.01uF  [SM-7351-CAP-0402]
C252  0.1uF  [SM-7351-CAP-0402]
C253  100pF  [SM-7351-CAP-0402]
C254  100pF  [SM-7351-CAP-0402]
J38  HEADER 5  [HEADER_5X1]
R502  33  [SM-7351-RES-0402]
R503  120  [SM-7351-RES-0402]
R504  33  [SM-7351-RES-0402]
U40  R1Z-3.305HP  [smd15x11-6-374m]
U41  ISO1050  [so9x6-8-191m]
U87  TPD1E10B06  [tpd1e10b06-2l]
U88  TPD1E10B06  [tpd1e10b06-2l]
sheet Pg29: Profibus
U1  AM5749ABZXEA  [BGA23X23-760-117M]  (sections -1,-10,-11,-12,-13,-14,-15,-16,-17,-18,-19,-2,-20,-21,-22,-23,-24,-25,-26,-27,-28,-29,-3,-4,-5,-6,-7,-8,-9)
sheet Pg30: RS-485
C449  0.1uF  [SM-7351-CAP-0402]
J39  HEADER 3  [header_3x1]
R582  0  [SM-7351-RES-0402]
R583  0  [SM-7351-RES-0402]
R584  0  [SM-7351-RES-0402]
R729  100  [SM-7351-RES-0402]
U77  SN65HVD78D  [soic_8]
U82  TPD1E10B06  [tpd1e10b06-2l]
U83  TPD1E10B06  [tpd1e10b06-2l]
sheet Pg34:Hardware
FID1  Fiducial  [Pad]
FID2  Fiducial  [Pad]
FID3  Fiducial  [Pad]
FID4  Fiducial  [Pad]
FID5  Fiducial  [Pad]
FID6  Fiducial  [Pad]
FID7  Fiducial  [Pad]
FID8  Fiducial  [Pad]
FID9  Fiducial  [Pad]
FID10  Fiducial  [Pad]
FID11  Fiducial  [Pad]
FID12  Fiducial  [Pad]
FID13  Fiducial  [Pad]
FID14  Fiducial  [Pad]
FID15  Fiducial  [Pad]
FID16  Fiducial  [Pad]
FID17  Fiducial  [Pad]
FID18  Fiducial  [Pad]
FID19  Fiducial  [Pad]
FID20  Fiducial  [Pad]
FID21  Fiducial  [Pad]
FID22  Fiducial  [Pad]
FID23  Fiducial  [Pad]
FID24  Fiducial  [Pad]
FID25  Fiducial  [Pad]
FID26  Fiducial  [Pad]
FID27  Fiducial  [Pad]
FID28  Fiducial  [Pad]
FID29  Fiducial  [Pad]
FID30  Fiducial  [Pad]
FID31  Fiducial  [Pad]
FID32  Fiducial  [Pad]
FID33  Fiducial  [Pad]
FID34  Fiducial  [Pad]
FID35  Fiducial  [Pad]
FID36  Fiducial  [Pad]
FID37  Fiducial  [Pad]
FID38  Fiducial  [Pad]
LBL1  THT-14-423-10
PCB1  PROC053  [DNP]

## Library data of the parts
C216 C219 C225-C230 C232-C236 C238-C240 C242 C251 C255-C258 C261-C264 C315 C408-C410 C420 C424-C429 C443 C444 C448 C480-C482 C488-C491 C493-C502 C506-C509 C511-C520 C524 = 1C_0.01uFCapacitor16V10%0402
C492 C510 = 1C_22uFCapacitor16V10%0805
C85 C87 C89 C90 C93 C94 C98-C100 C245 C252 C313 C314 C503-C505 C521-C523 C525-C531 C537-C539 C542 = C0402C104J4RACTU: DescriptiveText: CAP, CER, 0.1 uF, 16V, 5%, X7R, 0402; Mfr: KEMET
R754 R755 = 1R_240OhmResistor1_16W0402
U90 U91 = MT41K256M16HA-107
C84 C86 C543 C544 = 1C_0.001uFCapacitor50V5%0402
C88 C91 C92 C95-C97 C215 C222 C532 C534-C536 C540 C541 = 1C_10uFCapacitor16V10%0805
C101 C533 = 1C_10pFCapacitor50V1%smd0402
R45 R48 R412 R417 R420 R485 R494 R496 R561 R637 R741 R785 R786 R804 R805 R912 R913 = RMCF0402FT10K0: DescriptiveText: RES, THICK FILM,10K OHM, 1%, 0.063W, SMT0402; Mfr: STACKPOLE ELECTRONICS
R46 R47 R780 R781 = 1R_49.9OhmResistor1_16W0402
R49-R55 R57-R66 R68 R70-R75 R756-R779 R806 R807 = 1R_47ohm1_16W1%smd0402
R56 R782 = 1R_100KOhmResistor1_16W0402
R67 R410 R411 R416 R418 R451 R473-R478 R480-R483 R486 R487 R489 R492 R554 R555 R558 R559 R565-R567 R582-R586 R605-R628 R634-R636 R677 R682 R683 R783 R792 R795 R796 R906-R911 = 1R_ZeroOhmResistor1_16W0402
R69 R413 R784 = 1R_10ohm1_16W5%smd0402
U8 U92 = TPS51200DRCT
C217 C231 C237 C241 = 1C_4.7uFCapacitor16V10%0603
C218 = C2012X5R1H475M125AB: DescriptiveText: CAP, CER, 4.7UF, 50V, 20%, X5R, 0805; Mfr: TDK CORPORATION
C265 C350 C407 C484 = GRT155R61E105KE01D: DescriptiveText: CAP, CER, 1 UF, 10%, 25V, X5R, 0402; Mfr: MURATA
FB12 FB19 = 1L_FerBead_0
J16 = 2C_Conn_FFC_0.5mm_32pos
J17 = 2C_Conn_FFC_0.5mm_6pos
L1 = 1L_0.7Asmd
Q9 = 1Q_MOSFET_NChan_BSS138_0
R414 = 1R_47KOhmResistor1_16W0402
R415 = 1R_2OhmResistor1_10W1%0603
R630-R633 R687 = 1R_100ohm1_16W1%SMD0402: Cost100: 0.02; DescriptiveText: Resistor 100ohm 1/10W 1% 0402; Mfr: Panasonic; MfrNum: ERJ-2RKF1000X; PartName: 100ohm1/10W1%0402; TIIntPartnumber: 1R0246
TP18 TP24 = 2H_Testpoint_SMD1mmCircle
U32 = TPS61081DRCT
U76 = TPS71712DCKR
U89 = 1A_TC358778XBG
J24 = 2C_Conn_HDMI_TypeA
L29-L32 = 1M_DLW21SN900HQ2L_0
R495 R556 R563 = 1R_2.2KOhmResistor1_16W0402
R484 R491 R560 R562 = 1R_4.7KOhmResistor1_16W0402
U46 = TPD12S016PWR
C224 C479 = 1C_2.2uF16V10%SMD0805
C243 C244 = CGA2B2C0G1H180J050BA: DescriptiveText: CAP, CER, 18 PF, 50V, 5%, C0G, 0402; Mfr: TDK CORPORATION
D13 = 5988170107F
FB9-FB11 = MPZ1608S221ATA00
J19 = USB
R472 = 1R_ZeroOhmResistor1_16W0603
R479 = 1R_12Kohm1_16W1%SMD0402
R493 = 1R_220ohm1_10W1%smd0402
U34 = SN74LVC1G00DCKR
U35 = SN74LVC1G07DCKRE4
U36 = TPD2E001DRLR: DescriptiveText: IC, LOW-CAP 2-CHANNEL ESD PROTECTION ARRAY, SOT-5; Mfr: TEXAS INSTRUMENTS
U37 = 1A_FT2232_2
U38 = 1A_93C56EEPROM2Kbit
U63 = 1A_SN74AVC4T245
U65 U75 = SN74AVC2T244DQMR
Y5 = 1Y_Crystal12MHzABM3_0
R505-R513 = 1R_49.9KOhmResistor1_16W0402
U43 = 1A_EMMC16G_S100: Mfr: Micron; MfrNum: MTFC16GAKAECN-2M WT; PartName: MTFC16GAKAECN; Vendor: MICRON
C249 C250 = C1608X5R1C335K080AC: DescriptiveText: CAP, CER, 3.3UF, 16V, 10%,  X5R, 0603; Mfr: TDK
C253 C254 = 1C_100pFCapacitor16V10%0402
J38 = 2H_Header_5x1
R502 R504 = 1R_33ohmResistor1_16W5%0402
R503 = 1R_120ohm1_16W1%smd0402
U40 = 1A_IsoReg5V_R1Z-3.305HP
U41 = 1A_ISO1050
U82 U83 U87 U88 = TPD1E10B06DPYR
U1 = AM5749ABZXEA: DescriptiveText: Dual Cortex A15 Dual C66X SOC AM574x
C449 = C1005X7R1H104K050BE: DescriptiveText: CAP, CER, 0.1UF, 50V, 10%, X7R, 0402; Mfr: TDK CORPORATION
J39 = 2H_Header_3x1
R729 = 1R_100ohm1_10W1%SMD0402: DescriptiveText: Resistor 100ohm 1/10W 1% 0402; PartName: 100ohm1/10W1%0402
U77 = 1A_SN65HVD78
FID1-FID38 = Fiducial
LBL1 = THT-14-423-10: DescriptiveText: LABEL, Thermal Transfer Printable Labels, 0.650" W x 0.200" H; Mfr: BRADY
PCB1 = 3M_AM572xIDKEVMBarePCB: DescriptiveText: AM574x Industrial EVM Bare PCB; Mfr: ANY; PartName: AM574XIndustrialEVMBarePCB; Version: 1.1

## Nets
DGND: C84.2 C86.2 C88.2 C90.2 C91.2 C92.2 C93.2 C94.2 C95.2 C96.2 C97.2 C98.2 C99.2 C100.2 C101.2 C215.2 C216.2 C217.2 C218.2 C219.2 C222.2 C224.2 C225.2 C226.2 C227.2 C228.1 C229.2 C230.1 C231.1 C232.2 C233.2 C234.1 C235.2 C236.2 C237.1 C238.2 C239.2 C240.1 C241.2 C242.1 C243.2 C244.2 C245.2 C249.2 C251.2 C253.2 C254.2 C255.2 C256.2 C257.2 C258.2 C261.2 C262.2 C263.2 C264.2 C265.2 C313.2 C315.2 C350.2 C407.2 C408.2 C409.2 C410.2 C420.2 C424.2 C425.2 C426.2 C427.2 C428.2 C429.2 C443.2 C444.2 C448.2 C449.2 C479.2 C480.2 C481.2 C482.2 C484.2 C488.2 C489.2 C490.2 C491.2 C492.2 C493.2 C494.2 C495.2 C496.2 C497.2 C498.2 C499.2 C500.2 C501.2 C502.2 C504.2 C505.2 C506.2 C507.2 C508.2 C509.2 C510.2 C511.2 C512.2 C513.2 C514.2 C515.2 C516.2 C517.2 C518.2 C519.2 C520.2 C522.2 C523.2 C524.2 C525.2 C527.2 C528.2 C530.2 C531.2 C532.2 C533.2 C534.2 C535.2 C536.2 C537.2 C540.2 C541.2 C542.2 C543.2 C544.2 FB12.2 J16.7 J16.10 J16.13 J16.16 J16.19 J16.22 J16.MNT1 J16.MNT2 J17.6 J17.MNT1 J17.MNT2 J19.5(GND) J24.2(DAT2_S) J24.5(DAT1_S) J24.8(DAT0_S) J24.11(CLK_S) J24.17(DDC/CEC_GND) J24.MTG1 J24.MTG2 J24.MTG3 J24.MTG4 J39.3 Q9.S(SOURCE) R48.1 R414.1(P1) R415.1 R417.1 R479.2(P2) R484.1(P1) R489.1(P1) R494.1 R561.1 R754.1(P1) R755.1(P1) R785.1 R912.1 R913.1 U8.4(PGND) U8.8(GND) U8.11(PWRPD) U32.4(GND) U32.8(PGND) U32.PAD(TPAD) U34.3(GND) U35.3(GND) U36.4(GND) U37.1(GND.1) U37.5(GND.2) U37.10(AGND) U37.11(GND.3) U37.13(TEST) U37.15(GND.4) U37.25(GND.5) U37.35(GND.6) U37.47(GND.7) U37.51(GND.8) U38.5(VSS) U38.7(NC1) U40.1(VIN-) U41.4(GND1) U43.C4(VSSQ) U43.E7(VSS) U43.G5(VSS) U43.H10(VSS) U43.K8(VSS) U43.N2(VSSQ) U43.N5(VSSQ) U43.P4(VSSQ) U43.P6(VSSQ) U46.6(GND) U46.14(GND) U46.19(GND) U63.8(GND) U63.9(GND) U65.5(GND) U75.5(GND) U76.2(GND) U77.5(GND) U82.2 U83.2 U89.A1(VSS) U89.A10(VSS) U89.B7(VSS) U89.D4(VSS) U89.D5(VSS) U89.D6(VSS) U89.D7(VSS) U89.E4(VSS) U89.E5(VSS) U89.E6(VSS) U89.E7(VSS) U89.E9(VSS) U89.F4(VSS) U89.F5(VSS) U89.F6(VSS) U89.F7(VSS) U89.G4(VSS) U89.G5(VSS) U89.G6(VSS) U89.G7(VSS) U89.H2(VSS) U89.H9(VSS) U89.J4(VSS) U89.J5(VSS) U89.J8(CS) U89.K10(VSS) U90.A9(VSS) U90.B1(VSSQ) U90.B3(VSS) U90.B9(VSSQ) U90.D1(VSSQ) U90.D8(VSSQ) U90.E1(VSS) U90.E2(VSSQ) U90.E8(VSSQ) U90.F9(VSSQ) U90.G1(VSSQ) U90.G8(VSS) U90.G9(VSSQ) U90.J2(VSS) U90.J8(VSS) U90.M1(VSS) U90.M9(VSS) U90.P1(VSS) U90.P9(VSS) U90.T1(VSS) U90.T9(VSS) U91.A9(VSS) U91.B1(VSSQ) U91.B3(VSS) U91.B9(VSSQ) U91.D1(VSSQ) U91.D8(VSSQ) U91.E1(VSS) U91.E2(VSSQ) U91.E8(VSSQ) U91.F9(VSSQ) U91.G1(VSSQ) U91.G8(VSS) U91.G9(VSSQ) U91.J2(VSS) U91.J8(VSS) U91.M1(VSS) U91.M9(VSS) U91.P1(VSS) U91.P9(VSS) U91.T1(VSS) U91.T9(VSS) U92.4(PGND) U92.8(GND) U92.11(PWRPD) ; also on sheet 10 11 12 14 15 16 17 18 19 20 21 22 23 24 25 26 27 28 29 30 31 32 33 34
GND_CAN1: C250.2 C252.2 J38.4 U40.4(VOUT-) U40.5(VOUT-) U41.5(GND2) U87.2 U88.2
GNDUSBJ: FB12.1 J19.S1 J19.S2 J19.S3 J19.S4
V1_2D: C480.1 C481.1 C484.1 FB19.1 U76.5(OUT) U89.A7(VDDC) U89.B1(VDDC) U89.K4(VDDC)
V1_2D_EN: R451.1(P1) U76.3(EN)
V1_8D: R451.2(P2) ; also on sheet 20 23 26 28 30 33
V1_8FTDI: C227.1 C232.1 C235.1 C238.1 C241.1 U37.12(VCORE.1) U37.37(VCORE.2) U37.49(VREGOUT) U37.64(VCORE.3)
V3_3D: C88.1 C219.1 C249.1 C251.1 C255.1 C256.1 C257.1 C258.1 C261.1 C262.1 C263.1 C264.1 C350.1 C408.1 C409.1 C410.1 C420.1 C426.1 C428.1 C444.1 C449.1 C479.1 C532.1 J17.5 R56.2(P2) R67.2(P2) R410.2(P2) R412.2 R417.2 R420.1 R472.2(P2) R505.2(P2) R506.2(P2) R507.2(P2) R508.2(P2) R509.2(P2) R510.2(P2) R511.2(P2) R512.2(P2) R513.2(P2) R556.2(P2) R559.2(P2) R563.2(P2) R637.1 R741.2 R782.2(P2) R783.2(P2) R804.2 R805.2 U8.10(VIN) U40.2(VIN+) U41.1(VCC1) U43.C6(VCCQ) U43.E6(VCC) U43.F5(VCC) U43.J10(VCC) U43.K9(VCC) U43.M4(VCCQ) U43.N4(VCCQ) U43.P3(VCCQ) U43.P5(VCCQ) U46.24(VCCA) U63.16(VCCB) U65.8(VCCB) U75.1(VCCA) U75.3(A2) U77.8(VCC) U89.B10(VDDIO) U89.H1(VDDIO) U89.K5(VDDIO) U89.K9(VDDIO) U92.10(VIN) ; also on sheet 10 11 12 14 15 17 18 19 20 21 22 23 24 25 26 27 28 29 30 31 32 33 34
V3_3FTDI: C224.1 C228.2 C229.1 C230.2 C233.1 C236.1 C239.1 C242.2 C245.1 C425.1 C443.1 C448.1 FB10.2 FB11.2 R472.1(P1) R485.2 R496.2 U34.5(VCC) U35.5(VCC) U37.20(VCCIO.1) U37.31(VCCIO.2) U37.42(VCCIO.3) U37.50(VREGIN) U37.56(VCCIO.4) U38.6(NC2) U38.8(VCC) U63.1(VCCA) U63.2(1DIR) U63.3(2DIR) U65.1(VCCA) U75.8(VCCB)
V3_7LCD: C222.1 C315.1 J16.3 J16.4 J16.5 ; also on sheet 19
V5_0D: C427.1 R560.2(P2) R562.2(P2) U46.11(VCC5V) ; also on sheet 14 15 19 21 31
V5_0HDMICONN: C429.1 J24.18(+5V) U46.13(5V_OUT)
VDD_MIPI: C424.1 C482.1 FB19.2 U89.E10(VDD_MIPI) U89.H10(VDD_MIPI)
VDDR2_VREF: C503.2 C504.1 C505.1 C521.2 C522.1 C523.1 C524.1 C531.1 U1.N22(DDR2_VREF) U90.H1(VREFDQ) U90.M8(VREFCA) U91.H1(VREFDQ) U91.M8(VREFCA) U92.6(REFOUT)
VDDR2_VTT: C525.1 C526.1 C527.1 C528.1 C530.1 C534.1 C535.1 C536.1 C537.1 C538.1 C539.1 R756.1(P1) R757.1(P1) R758.1(P1) R759.1(P1) R760.1(P1) R761.1(P1) R762.1(P1) R763.1(P1) R764.1(P1) R765.1(P1) R766.1(P1) R767.1(P1) R768.1(P1) R769.1(P1) R770.1(P1) R771.1(P1) R772.1(P1) R773.1(P1) R774.1(P1) R775.1(P1) R776.1(P1) R777.1(P1) R778.1(P1) R779.1(P1) R784.2(P2) R807.1(P1) U92.3(VO)
VDDR_VREF: C99.1 U8.6(REFOUT) ; also on sheet 16
VDDR_VTT: C87.1 C89.1 C93.1 C94.1 C95.1 C96.1 C97.1 C98.1 C100.1 C313.1 C314.1 R49.1(P1) R50.1(P1) R51.1(P1) R52.1(P1) R53.1(P1) R54.1(P1) R55.1(P1) R57.1(P1) R58.1(P1) R59.1(P1) R60.1(P1) R61.1(P1) R62.1(P1) R63.1(P1) R64.1(P1) R65.1(P1) R66.1(P1) R68.1(P1) R69.2(P2) R70.1(P1) R71.1(P1) R72.1(P1) R73.1(P1) R74.1(P1) R75.1(P1) R806.1(P1) U8.3(VO)
VDDS_DDR: C84.1 C85.2 C87.2 C89.2 C90.1 C91.1 C92.1 C314.2 C488.1 C489.1 C490.1 C491.1 C492.1 C493.1 C494.1 C495.1 C496.1 C497.1 C498.1 C499.1 C500.1 C501.1 C502.1 C503.1 C506.1 C507.1 C508.1 C509.1 C510.1 C511.1 C512.1 C513.1 C514.1 C515.1 C516.1 C517.1 C518.1 C519.1 C520.1 C521.1 C526.2 C529.2 C538.2 C539.2 C540.1 C541.1 C542.1 C543.1 R45.2 R786.2 U8.2(VLDOIN) U90.A1(VDDQ) U90.A8(VDDQ) U90.B2(VDD) U90.C1(VDDQ) U90.C9(VDDQ) U90.D2(VDDQ) U90.D9(VDD) U90.E9(VDDQ) U90.F1(VDDQ) U90.G7(VDD) U90.H2(VDDQ) U90.H9(VDDQ) U90.K2(VDD) U90.K8(VDD) U90.N1(VDD) U90.N9(VDD) U90.R1(VDD) U90.R9(VDD) U91.A1(VDDQ) U91.A8(VDDQ) U91.B2(VDD) U91.C1(VDDQ) U91.C9(VDDQ) U91.D2(VDDQ) U91.D9(VDD) U91.E9(VDDQ) U91.F1(VDDQ) U91.G7(VDD) U91.H2(VDDQ) U91.H9(VDDQ) U91.K2(VDD) U91.K8(VDD) U91.N1(VDD) U91.N9(VDD) U91.R1(VDD) U91.R9(VDD) U92.2(VLDOIN) ; also on sheet 16 19 23
AM57XX_GPIO_RS485: R584.2(P2) U1.AA3(MCASP5_ACLKX/PR2_PRU1_R30_1)
AM57XX_HDMI_CLK+: L29.4 U1.AH16(HDMI1_CLOCKY)
AM57XX_HDMI_CLK-: L29.1 U1.AG16(HDMI1_CLOCKX)
AM57XX_HDMI_TX0+: L30.4 U1.AH17(HDMI1_DATA0Y)
AM57XX_HDMI_TX0-: L30.1 U1.AG17(HDMI1_DATA0X)
AM57XX_HDMI_TX1+: L31.4 U1.AH18(HDMI1_DATA1Y)
AM57XX_HDMI_TX1-: L31.1 U1.AG18(HDMI1_DATA1X)
AM57XX_HDMI_TX2+: L32.4 U1.AH19(HDMI1_DATA2Y)
AM57XX_HDMI_TX2-: L32.1 U1.AG19(HDMI1_DATA2X)
AM57XX_LCD_DE: R634.2(P2) U1.B10(VOUT1_DE)
AM57XX_LCD_HSYNC: R636.2(P2) U1.C11(VOUT1_HSYNC)
AM57XX_LCD_PCLK: R565.2(P2) U1.D11(VOUT1_CLK)
AM57XX_LCD_VSYNC: R635.2(P2) U1.E11(VOUT1_VSYNC)
AM57XX_UART2_RXD: R583.2(P2) U1.D28(UART2_RXD)
AM57XX_UART2_TXD: R582.2(P2) U1.D26(UART2_TXD)
AM57XX_UART3_RXD: R487.1(P1) U1.D27(UART2_CTSn/UART3_RXD)
AM57XX_UART3_TXD: R486.1(P1) U1.C28(UART2_RTSn/UART3_TXD)
AM57XX_VOUT1_D0: R605.2(P2) U1.F11(VOUT1_D0)
AM57XX_VOUT1_D1: R606.2(P2) U1.G10(VOUT1_D1)
AM57XX_VOUT1_D2: R607.2(P2) U1.F10(VOUT1_D2) ; also on sheet 10
AM57XX_VOUT1_D3: R608.2(P2) U1.G11(VOUT1_D3) ; also on sheet 10
AM57XX_VOUT1_D4: R609.2(P2) U1.E9(VOUT1_D4) ; also on sheet 10
AM57XX_VOUT1_D5: R610.2(P2) R910.2(P2) U1.F9(VOUT1_D5) ; also on sheet 10
AM57XX_VOUT1_D6: R612.2(P2) R911.2(P2) U1.F8(VOUT1_D6) ; also on sheet 10
AM57XX_VOUT1_D7: R611.2(P2) R908.2(P2) U1.E7(VOUT1_D7) ; also on sheet 10
AM57XX_VOUT1_D8: R613.2(P2) R909.2(P2) U1.E8(VOUT1_D8)
AM57XX_VOUT1_D9: R614.2(P2) U1.D9(VOUT1)
AM57XX_VOUT1_D10: R616.2(P2) U1.D7(VOUT1_D10) ; also on sheet 10
AM57XX_VOUT1_D11: R615.2(P2) U1.D8(VOUT1_D11) ; also on sheet 10
AM57XX_VOUT1_D12: R617.2(P2) U1.A5(VOUT1_D12) ; also on sheet 10
AM57XX_VOUT1_D13: R619.2(P2) R906.2(P2) U1.C6(VOUT1_D13) ; also on sheet 10
AM57XX_VOUT1_D14: R620.2(P2) R907.2(P2) U1.C8(VOUT1_D14) ; also on sheet 10
AM57XX_VOUT1_D15: R618.2(P2) U1.C7(VOUT1_D15) ; also on sheet 10
AM57XX_VOUT1_D16: R621.2(P2) U1.B7(VOUT1_D16)
AM57XX_VOUT1_D17: R622.2(P2) U1.B8(VOUT1_D17)
AM57XX_VOUT1_D18: R624.2(P2) U1.A7(VOUT1_D18) ; also on sheet 10
AM57XX_VOUT1_D19: R623.2(P2) U1.A8(VOUT1_D19) ; also on sheet 10
AM57XX_VOUT1_D20: R625.2(P2) U1.C9(VOUT1_D20) ; also on sheet 10
AM57XX_VOUT1_D21: R627.2(P2) U1.A9(VOUT1_D21) ; also on sheet 10
AM57XX_VOUT1_D22: R628.2(P2) U1.B9(VOUT1_D22) ; also on sheet 10
AM57XX_VOUT1_D23: R626.2(P2) U1.A10(VOUT1_D23) ; also on sheet 10
AM572X_DCAN1_RX: C253.1 R502.1 U1.G19(DCAN1_RX)
AM572X_DCAN1_TX: R504.1 U1.G20(DCAN1_TX)
AM572X_HDMI_CEC: R683.2(P2) R805.1 U1.B20(SPI1_CS3/HDMI_CEC)
AM572X_HDMI_DDC_SCL: R556.1(P1) R795.2(P2) U1.C25(I2C2_SDA/HDMI1_DDC_SCL) ; also on sheet 28
AM572X_HDMI_DDC_SDA: R563.1(P1) R796.2(P2) U1.F17(I2C2_SCL/HDMI1_DDC_SDA) ; also on sheet 28
AM572X_HDMI_HPD: R682.2(P2) R804.1 U1.B21(SPI1_CS2/HDMI_HPD)
BKLT_EN: Q9.G(GATE) R412.1 R416.1(P1)
BKLT_L: L1.1 U32.1(L)
BKLT_SW: L1.2 U32.10(SW)
CAN1_H: J38.2 R503.2(P2) U41.7(CANH) U88.1
CAN1_L: J38.3 R503.1(P1) U41.6(CANL) U87.1
CAN1_RXDF: R502.2 U41.2(RXD) ; also on sheet 31
CAN1_TXDF: C254.1 R504.2 U41.3(TXD) ; also on sheet 31
DDR2_A0: R761.2(P2) U1.R25(DDR2_A0) U90.N3(A0) U91.N3(A0)
DDR2_A1: R763.2(P2) U1.R26(DDR2_A1) U90.P7(A1) U91.P7(A1)
DDR2_A2: R762.2(P2) U1.R28(DDR2_A2) U90.P3(A2) U91.P3(A2)
DDR2_A3: R765.2(P2) U1.R27(DDR2_A3) U90.N2(A3) U91.N2(A3)
DDR2_A4: R764.2(P2) U1.P23(DDR2_A4) U90.P8(A4) U91.P8(A4)
DDR2_A5: R766.2(P2) U1.P22(DDR2_A5) U90.P2(A5) U91.P2(A5)
DDR2_A6: R768.2(P2) U1.P25(DDR2_A6) U90.R8(A6) U91.R8(A6)
DDR2_A7: R767.2(P2) U1.N20(DDR2_A7) U90.R2(A7) U91.R2(A7)
DDR2_A8: R770.2(P2) U1.P27(DDR2_A8) U90.T8(A8) U91.T8(A8)
DDR2_A9: R769.2(P2) U1.N27(DDR2_A9) U90.R3(A9) U91.R3(A9)
DDR2_A10: R771.2(P2) U1.N23(DDR2_A10) U90.L7(A10/AP) U91.L7(A10/AP)
DDR2_A11: R773.2(P2) U1.P26(DDR2_A11) U90.R7(A11) U91.R7(A11)
DDR2_A12: R772.2(P2) U1.N28(DDR2_A12) U90.N7(A12/~{BC}) U91.N7(A12/~{BC})
DDR2_A13: R775.2(P2) U1.T22(DDR2_A13) U90.T3(A13) U91.T3(A13)
DDR2_A14: R774.2(P2) U1.R22(DDR2_A14) U90.T7(A14) U91.T7(A14)
DDR2_A15: R807.2(P2) U1.U22(DDR2_A15) U90.M7(NU4) U91.M7(NU4)
DDR2_BA0: R777.2(P2) U1.U23(DDR2_BA0) U90.M2(BA0) U91.M2(BA0)
DDR2_BA1: R776.2(P2) U1.U27(DDR2_BA1) U90.N8(BA1) U91.N8(BA1)
DDR2_BA2: R779.2(P2) U1.U26(DDR2_BA2) U90.M3(BA2) U91.M3(BA2)
DDR2_CASn: R759.2(P2) U1.U28(DDR2_CASn) U90.K3(CASn) U91.K3(CASn)
DDR2_CKE: R756.2(P2) U1.U24(DDR2_CKE) U90.K9(CKE) U91.K9(CKE)
DDR2_CLK: R780.2(P2) U1.T28(DDR2_CK) U90.J7(CK) U91.J7(CK)
DDR2_CLKn: R781.2(P2) U1.T27(DDR2_CKn) U90.K7(CKn) U91.K7(CKn)
DDR2_CS0n: R757.2(P2) U1.P24(DDR2_CSN0) U90.L2(CSn) U91.L2(CSn)
DDR2_D0: U1.E26(DDR2_D0) U90.E3(DQ0)
DDR2_D1: U1.G25(DDR2_D1) U90.F2(DQ2)
DDR2_D2: U1.F25(DDR2_D2) U90.G2(DQ6)
DDR2_D3: U1.F24(DDR2_D3) U90.H3(DQ4)
DDR2_D4: U1.F26(DDR2_D4) U90.F7(DQ1)
DDR2_D5: U1.F27(DDR2_D5) U90.H8(DQ5)
DDR2_D6: U1.E27(DDR2_D6) U90.F8(DQ3)
DDR2_D7: U1.E28(DDR2_D7) U90.H7(DQ7)
DDR2_D8: U1.H23(DDR2_D8) U90.D7(DQ8)
DDR2_D9: U1.H25(DDR2_D9) U90.A2(DQ13)
DDR2_D10: U1.H24(DDR2_D10) U90.C3(DQ9)
DDR2_D11: U1.H26(DDR2_D11) U90.A3(DQ15)
DDR2_D12: U1.G26(DDR2_D12) U90.C2(DQ11)
DDR2_D13: U1.J25(DDR2_D13) U90.B8(DQ14)
DDR2_D14: U1.J26(DDR2_D14) U90.A7(DQ12)
DDR2_D15: U1.J24(DDR2_D15) U90.C8(DQ10)
DDR2_D16: U1.L22(DDR2_D16) U91.E3(DQ0)
DDR2_D17: U1.K20(DDR2_D17) U91.H8(DQ5)
DDR2_D18: U1.K21(DDR2_D18) U91.H3(DQ4)
DDR2_D19: U1.L23(DDR2_D19) U91.F7(DQ1)
DDR2_D20: U1.L24(DDR2_D20) U91.F8(DQ3)
DDR2_D21: U1.J23(DDR2_D21) U91.F2(DQ2)
DDR2_D22: U1.K22(DDR2_D22) U91.G2(DQ6)
DDR2_D23: U1.J20(DDR2_D23) U91.H7(DQ7)
DDR2_D24: U1.L27(DDR2_D24) U91.D7(DQ8)
DDR2_D25: U1.L26(DDR2_D25) U91.A3(DQ15)
DDR2_D26: U1.L25(DDR2_D26) U91.C2(DQ11)
DDR2_D27: U1.L28(DDR2_D27) U91.A7(DQ12)
DDR2_D28: U1.M23(DDR2_D28) U91.C8(DQ10)
DDR2_D29: U1.M24(DDR2_D29) U91.A2(DQ13)
DDR2_D30: U1.M25(DDR2_D30) U91.C3(DQ9)
DDR2_D31: U1.M26(DDR2_D31) U91.B8(DQ14)
DDR2_DQM0: U1.F28(DDR2_DQM0) U90.E7(LDM)
DDR2_DQM1: U1.G24(DDR2_DQM1) U90.D3(UDM)
DDR2_DQM2: U1.K23(DDR2_DQM2) U91.E7(LDM)
DDR2_DQM3: U1.M22(DDR2_DQM3) U91.D3(UDM)
DDR2_DQS0: U1.G28(DDR2_DQS0) U90.F3(LDQS)
DDR2_DQS1: U1.H27(DDR2_DQS1) U90.C7(UDQS)
DDR2_DQS2: U1.K27(DDR2_DQS2) U91.F3(LDQS)
DDR2_DQS3: U1.M28(DDR2_DQS3) U91.C7(UDQS)
DDR2_DQSn0: U1.G27(DDR2_DQS0n) U90.G3(LDQSn)
DDR2_DQSn1: U1.H28(DDR2_DQS1n) U90.B7(UDQSn)
DDR2_DQSn2: U1.K28(DDR2_DQS2n) U91.G3(LDQSn)
DDR2_DQSn3: U1.M27(DDR2_DQS3n) U91.B7(UDQSn)
DDR2_ODT: R778.2(P2) U1.R23(DDR2_ODT0) U90.K1(ODT) U91.K1(ODT)
DDR2_RASn: R758.2(P2) U1.T23(DDR2_RASn) U90.J3(RASn) U91.J3(RASn)
DDR2_RESETn: R913.2 U1.R24(DDR2_RST) U90.T2(RESETn) U91.T2(RESETn)
DDR2_WEn: R760.2(P2) U1.U25(DDR2_WEn) U90.L3(WEn) U91.L3(WEn)
DDR_A0: R54.2(P2) ; also on sheet 16
DDR_A1: R57.2(P2) ; also on sheet 16
DDR_A2: R55.2(P2) ; also on sheet 16
DDR_A3: R58.2(P2) ; also on sheet 16
DDR_A4: R59.2(P2) ; also on sheet 16
DDR_A5: R60.2(P2) ; also on sheet 16
DDR_A6: R61.2(P2) ; also on sheet 16
DDR_A7: R62.2(P2) ; also on sheet 16
DDR_A8: R63.2(P2) ; also on sheet 16
DDR_A9: R64.2(P2) ; also on sheet 16
DDR_A10: R66.2(P2) ; also on sheet 16
DDR_A11: R65.2(P2) ; also on sheet 16
DDR_A12: R68.2(P2) ; also on sheet 16
DDR_A13: R70.2(P2) ; also on sheet 16
DDR_A14: R71.2(P2) ; also on sheet 16
DDR_A15: R806.2(P2) ; also on sheet 16
DDR_BA0: R72.2(P2) ; also on sheet 16
DDR_BA1: R73.2(P2) ; also on sheet 16
DDR_BA2: R74.2(P2) ; also on sheet 16
DDR_CASn: R52.2(P2) ; also on sheet 16
DDR_CKE: R49.2(P2) ; also on sheet 16
DDR_CLK: R46.2(P2) ; also on sheet 16
DDR_CLKn: R47.2(P2) ; also on sheet 16
DDR_CS0n: R50.2(P2) ; also on sheet 16
DDR_ODT: R75.2(P2) ; also on sheet 16
DDR_RASn: R51.2(P2) ; also on sheet 16
DDR_RESETn: R912.2 ; also on sheet 16
DDR_WEn: R53.2(P2) ; also on sheet 16
EECS: U37.63(EECS) U38.1(CS)
EEDATA: R495.1(P1) U37.61(EEDATA) U38.3(DI)
EESK: U37.62(EESK) U38.2(CLK)
eMMC_RSTn: R741.1 U43.K5(RSTn) ; also on sheet 31
EMU_USB_DM: J19.2(DM) U36.5(IO2) U37.7(DM)
EMU_USB_DP: J19.3(DP) U36.3(IO1) U37.8(DP)
F_ADBUS0: R474.2(P2) U37.16(ADBUS0)
F_ADBUS1: R475.2(P2) U37.17(ADBUS1)
F_ADBUS2: R480.2(P2) U37.18(ADBUS2)
F_ADBUS3: R481.2(P2) U37.19(ADBUS3)
F_ADBUS4: R476.2(P2) U37.21(ADBUS4)
F_ADBUS5: R478.2(P2) U37.26(ACBUS0)
F_ADBUS6: R477.2(P2) U37.23(ADBUS6)
F_ADBUS7: R483.2(P2) U37.30(ACBUS4)
FT_SRESET: R478.1(P1) R484.2(P2) U34.1(A)
FT_SRESETB: R473.2(P2) U35.4(Y)
FT_SRESETn: U34.4(Y) U35.2(A)
FT_VBUS: R492.1(P1) U34.2(B)
FTDI_REF: R479.1(P1) U37.6(REF)
FTDI_VPHY: C231.2 C234.2 FB10.1 U37.4(VPHY)
FTDI_VPLL: C237.2 C240.2 FB11.1 U37.9(VPLL)
GPIO_TOUCH_RESETn: R792.2(P2) ; also on sheet 31
HDMI_CEC: R683.1(P1) U46.1(CEC_A)
HDMI_CLK+: J24.10(CLK+) L29.3 U46.16(TMDS_CK+)
HDMI_CLK-: J24.12(CLK-) L29.2 U46.15(TMDS_CK-)
HDMI_CT_HPD: R558.2(P2) R559.1(P1) U46.12(CT_HPD)
HDMI_DDC_SCL: R795.1(P1) U46.2(SCL_A)
HDMI_DDC_SDA: R796.1(P1) U46.3(SDA_A)
HDMI_HPLG: R682.1(P1) U46.4(HPD_A)
HDMI_LSOE: R558.1(P1) U46.5(LS_OE)
HDMI_TX0+: J24.7(DAT0+) L30.3 U46.18(TMDS_D0+)
HDMI_TX0-: J24.9(DAT0-) L30.2 U46.17(TMDS_D0-)
HDMI_TX1+: J24.4(DAT1+) L31.3 U46.21(TMDS_D1+)
HDMI_TX1-: J24.6(DAT1-) L31.2 U46.20(TMDS_D1-)
HDMI_TX2+: J24.1(DAT2+) L32.3 U46.23(TMDS_D2+)
HDMI_TX2-: J24.3(DAT2-) L32.2 U46.22(TMDS_D2-)
HDMICONN_CEC: J24.13(CEC) U46.7(CEC_B)
HDMICONN_HPLG: J24.19(HPLG) R561.2 U46.10(HPD_B)
HDMICONN_I2CSCL: J24.15(SCL) R560.1(P1) U46.8(SCL_B)
HDMICONN_I2CSDA: J24.16(SDA) R562.1(P1) U46.9(SDA_B)
IND_I2C_SCL: J17.2 R567.2(P2) ; also on sheet 10 11 18 20 21 26 31
IND_I2C_SDA: J17.1 R585.2(P2) ; also on sheet 10 11 18 20 21 26 31
JTAG_EMU0: R554.1(P1) ; also on sheet 10
JTAG_EMU1: R555.1(P1) ; also on sheet 10
JTAG_TCK: U63.13(1B1) ; also on sheet 10
JTAG_TDI: U63.12(1B2) ; also on sheet 10
JTAG_TDO: U75.2(A1) ; also on sheet 10
JTAG_TMS: U63.11(2B1) ; also on sheet 10
JTAG_TRSTn: U63.10(2B2) ; also on sheet 10
JTAGPOD_PRES: R677.1(P1) ; also on sheet 10
LCD_B0: R605.1(P1) U89.J3(PD0)
LCD_B1: R606.1(P1) U89.K3(PD1)
LCD_B2: R607.1(P1) U89.J2(PD2)
LCD_B3: R608.1(P1) U89.K2(PD3)
LCD_B4: R609.1(P1) U89.J1(PD4)
LCD_B5: R610.1(P1) U89.K1(PD5)
LCD_B6: R612.1(P1) U89.G2(PD6)
LCD_B7: R611.1(P1) U89.G1(PD7)
LCD_BACKLIGHT: R416.2(P2) U1.D1(VIN2A_D2/eCAP1_IN_PWM1)
LCD_CLKN: J16.20 R632.1(P1) U89.F10(MIPI_CN)
LCD_CLKP: J16.21 R632.2(P2) U89.F9(MIPI_CP)
LCD_DEN: R634.1(P1) U89.J7(DE)
LCD_G0: R613.1(P1) U89.F2(PD8)
LCD_G1: R614.1(P1) U89.F1(PD9)
LCD_G2: R616.1(P1) U89.E2(PD10)
LCD_G3: R615.1(P1) U89.E1(PD11)
LCD_G4: R617.1(P1) U89.D2(PD12)
LCD_G5: R619.1(P1) U89.D1(PD13)
LCD_G6: R620.1(P1) U89.C2(PD14)
LCD_G7: R618.1(P1) U89.C1(PD15)
LCD_HS: R636.1(P1) U89.K8(HSYNC)
LCD_MIPI0N: J16.17 R630.2(P2) U89.J10(MIPI_D0N)
LCD_MIPI0P: J16.18 R630.1(P1) U89.J9(MIPI_D0P)
LCD_MIPI1N: J16.14 R631.2(P2) U89.G10(MIPI_D1N)
LCD_MIPI1P: J16.15 R631.1(P1) U89.G9(MIPI_D1P)
LCD_MIPI2N: J16.11 R633.1(P1) U89.D10(MIPI_D2N)
LCD_MIPI2P: J16.12 R633.2(P2) U89.D9(MIPI_D2P)
LCD_MIPI3N: J16.8 R687.1(P1) U89.C10(MIPI_D3N)
LCD_MIPI3P: J16.9 R687.2(P2) U89.C9(MIPI_D3P)
LCD_PCLK: R565.1(P1) U89.J6(PCLK)
LCD_R0: R621.1(P1) U89.B2(PD16)
LCD_R1: R622.1(P1) U89.A2(PD17)
LCD_R2: R624.1(P1) U89.B3(PD18)
LCD_R3: R623.1(P1) U89.A3(PD19)
LCD_R4: R625.1(P1) U89.B4(PD20)
LCD_R5: R627.1(P1) U89.A4(PD21)
LCD_R6: R628.1(P1) U89.B5(PD22)
LCD_R7: R626.1(P1) U89.A5(PD23)
LCD_VS: R635.1(P1) U89.K7(VSYNC)
MMC2_CLK: U1.J7(GPMC_A23/MMC2_CLK) U43.M6(CLK)
MMC2_CMD: R513.1(P1) U1.H6(GPMC_CS1/MMC2_CMD) U43.M5(CMD)
MMC2_DAT0: R505.1(P1) U1.J4(GPMC_A24/MMC2_DAT0) U43.A3(DAT0)
MMC2_DAT1: R506.1(P1) U1.J6(GPMC_A25/MMC2_DAT1) U43.A4(DAT1)
MMC2_DAT2: R507.1(P1) U1.H4(GPMC_A26/MMC2_DAT2) U43.A5(DAT2)
MMC2_DAT3: R508.1(P1) U1.H5(GPMC_A27/MMC2_DAT3) U43.B2(DAT3)
MMC2_DAT4: R509.1(P1) U1.K7(GPMC_A19/MMC2_DAT4) U43.B3(DAT4)
MMC2_DAT5: R510.1(P1) U1.M7(GPMC_A20/MMC2_DAT5) U43.B4(DAT5)
MMC2_DAT6: R511.1(P1) U1.J5(GPMC_A21/MMC2_DAT6) U43.B5(DAT6)
MMC2_DAT7: R512.1(P1) U1.K6(GPMC_A22/MMC2_DAT7) U43.B6(DAT7)
PR2_EDC_LATCH0: R910.1(P1) ; also on sheet 31
PR2_EDC_LATCH1: R911.1(P1) ; also on sheet 31
PR2_EDC_SYNC0: R908.1(P1) ; also on sheet 31
PR2_EDC_SYNC1: R909.1(P1) ; also on sheet 31
PR2_UART0_RXD: R906.1(P1) ; also on sheet 31
PR2_UART0_TXD: R907.1(P1) ; also on sheet 31
RS485_A: J39.1 R729.2(P2) U77.6(A) U82.1
RS485_B: J39.2 R729.1(P1) U77.7(B) U83.1
SRCCLK: R586.2(P2) ; also on sheet 11
SYS_RESETn: R566.2(P2) ; also on sheet 25 31 32
SYS_WARMRESETn: R473.1(P1) ; also on sheet 10 32
TOUCH_INT: R418.2(P2) ; also on sheet 31
TSC_INT: J17.4 R418.1(P1)
TSC_RESETn: J17.3 R420.2 R792.1(P1)
UARTx_RXD: R487.2(P2) U37.38(BDBUS0)
UARTx_TXD: R486.2(P2) U37.39(BDBUS1)
USBJTAG_ENn: R677.2(P2) U63.14(2~{OE}) U63.15(1~{OE}) U65.4(~{OE}) U75.4(~{OE})
VCAN1: C250.1 C252.1 J38.1 U40.7(VOUT+) U41.8(VCC2)
VLED+: C215.1 C216.1 C218.1 J16.29 J16.30 U32.9(OUT)
VLED-: J16.23 J16.24 J16.25 J16.26 J16.27 J16.28 R415.2 U32.5(FB)
VMAIN: C217.1 C407.1 R411.2(P2) U32.2(VIN) U76.1(IN) ; also on sheet 11 19 20 31
VUSB_FTDI: C226.1 D13.2(Anode) FB9.2 R491.2(P2)
VUSB_JTAG: C225.1 FB9.1 J19.1(VBUS) U36.1(VCC)
XTIN: C243.1 U37.2(XTIN) Y5.1
XTOUT: C244.1 U37.3(XTOUT) Y5.2
N11217419: C85.1 R46.1(P1) R47.1(P1)
N11219802: R67.1(P1) U8.7(EN)
N11219922: R56.1(P1) U8.9(PGOOD)
N11219986: C101.1 R69.1(P1) U8.5(VOSNS)
N11220684: C86.1 R45.1 R48.2 U8.1(REFIN)
N12957779: R482.2(P2) U37.28(ACBUS2)
N12957783: R482.1(P1) U75.6(B2)
N12957791: R489.2(P2) U37.32(ACBUS5)
N12957851: R491.1(P1) R492.2(P2) R494.2 U37.59(BCBUS7)
N12958009: R485.1 U37.14(RESET#)
N12958129: D13.1(Cathode) R493.2
N12958219: R495.2(P2) R496.1 U38.4(DO)
N12958339: TP18.1 U37.36(SUSPEND#)
N12958347: R493.1 U37.60(PWREN#)
N12958879: R474.1(P1) U63.4(1A1)
N12958935: R476.1(P1) U63.7(2A2)
N12958939: R481.1(P1) U63.6(2A1)
N12958943: R480.1(P1) U75.7(B1)
N12958955: R475.1(P1) U63.5(1A2)
N17732522: R410.1(P1) U32.6(EN)
N17732526: R413.2(P2) R414.2(P2) U32.3(SS)
N17732536: Q9.D(DRAIN) R413.1(P1)
N17732560: R411.1(P1) U32.7(FSW)
N19388440: R566.1(P1) U89.B9(RESXn)
N19438966: R582.1(P1) U1.AB9(MCASP5_FSX/PR2_PRU1_R31_2) U77.4(D)
N19438972: R583.1(P1) U77.1(R)
N19438984: R584.1(P1) U77.2(~{RE}) U77.3(DE)
N20144297: R637.2 U89.A9(MSEL)
N20706534: R554.2(P2) U65.7(B1)
N20706536: R555.2(P2) U65.6(B2)
N20706626: R477.1(P1) U65.2(A1)
N20706635: R483.1(P1) U65.3(A2)
N21099488: C265.1 U43.C2(VDDI)
N21306186: TP24.1 U89.B6(GPIO1)
N21306311: R567.1(P1) U89.A8(I2C_SCL)
N21306314: R585.1(P1) U89.B8(I2C_SDA)
N21307911: R586.1(P1) U89.K6(REFCLK)
N21519094: R754.2(P2) U90.L8(ZQ)
N21519152: R755.2(P2) U91.L8(ZQ)
N21552786: C544.1 R785.2 R786.1 U92.1(REFIN)
N21553219: C529.1 R780.1(P1) R781.1(P1)
N21553307: R783.1(P1) U92.7(EN)
N21553371: R782.1(P1) U92.9(PGOOD)
N21553379: C533.1 R784.1(P1) U92.5(VOSNS)

Not connected (* = marked no-connect by the designer): J16 1* 2* 6* 31* 32*; J19 4(ID)*; J24 14(NC)*; J38 5*; U35 1(NC)*; U36 2(NC)*; U37 22(ADBUS5)* 24(ADBUS7)* 27(ACBUS1)* 29(ACBUS3)* 33(ACBUS6)* 34(ACBUS7)* 40(BDBUS2)* 41(BDBUS3)* 43(BDBUS4)* 44(BDBUS5)* 45(BDBUS6)* 46(BDBUS7)* 48(BCBUS0)* 52(BCBUS1)* 53(BCBUS2)* 54(BCBUS3)* 55(BCBUS4)* 57(BCBUS5)* 58(BCBUS6)*; U40 10(NC)*; U43 A1(NCA1)* A2(NCA2)* A6(RFUA6)* A7(RFUA7)* A8(NCA8)* A9(NCA9)* A10(NCA10)* A11(NCA11)* A12(NCA12)* A13(NCA13)* A14(NCA14)* B1(NCB1)* B7(NCB7)* B8(NCB8)* B9(NCB9)* B10(NCB10)* B11(NCB11)* B12(NCB12)* B13(NCB13)* B14(NCB14)* C1(NCC1)* C3(NCC3)* C5(NCC5)* C7(NCC7)* C8(NCC8)* C9(NCC9)* C10(NCC10)* C11(NCC11)* C12(NCC12)* C13(NCC13)* C14(NCC14)* D1(NCD1)* D2(NCD2)* D3(NCD3)* D4(NCD4)* D12(NCD12)* D13(NCD13)* D14(NCD14)* E1(NCE1)* E2(NCE2)* E3(NCE3)* E5(RFUE5)* E8(RFUE8)* E9(RFUE9)* E10(RFUE10)* E12(NCE12)* E13(NCE13)* E14(NCE14)* F1(NCF1)* F2(NCF2)* F3(NCF3)* F10(RFUF10)* F12(NCF12)* F13(NCF13)* F14(NCF14)* G1(NCG1)* G2(NCG2)* G3(RFUG3)* G10(RFUG10)* G12(NCG12)* G13(NCG13)* G14(NCG14)* H1(NCH1)* H2(NCH2)* H3(NCH3)* H5(RFUH5)* H12(NCH12)* H13(NCH13)* H14(NCH14)* J1(NCJ1)* J2(NCJ2)* J3(NCJ3)* J5(RFUJ5)* J12(NCJ12)* J13(NCJ13)* J14(NCJ14)* K1(NCK1)* K2(NCK2)* K3(NCK3)* K6(RFUK6)* K7(RFUK7)* K10(RFUK10)* K12(NCK12)* K13(NCK13)* K14(NCK14)* L1(NCL1)* L2(NCL2)* L3(NCL3)* L12(NCL12)* L13(NCL13)* L14(NCL14)* M1(NCM1)* M2(NCM2)* M3(NCM3)* M7(NCM7)* M8(NCM8)* M9(NCM9)* M10(NCM10)* M11(NCM11)* M12(NCM12)* M13(NCM13)* M14(NCM14)* N1(NCN1)* N3(NCN3)* N6(NCN6)* N7(NCN7)* N8(NCN8)* N9(NCN9)* N10(NCN10)* N11(NCN11)* N12(NCN12)* N13(NCN13)* N14(NCN14)* P1(NCP1)* P2(NCP2)* P7(RFUP7)* P8(NCP8)* P9(NCP9)* P10(RFUP10)* P11(NCP11)* P12(NCP12)* P13(NCP13)* P14(NCP14)*; U76 4(NR)*; U89 A6(GPIO2)*; U90 J1(NU0) J9(NU1) L1(NU2) L9(NU3); U91 J1(NU0) J9(NU1) L1(NU2) L9(NU3)

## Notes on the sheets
sheet 2
- USB JTAG
sheet 5
- LCD Module
- BackLight Power
sheet 6
- eMMC Memory
sheet 7
- Assembly Notes:
  1.  These assemblies are ESD sensitive.
  ESD precautians shall be observed.
  2.  These assemblies must be clean and
  free from flux and all contaminants.  Use
  of 'no clean flux' is not acceptable.
  3.  These assemblies must comply with
  workmanship standard IPC-A-610 Class 2,
  unless otherwise specified.
  4.  Each finished board will receive a
  serial number  sticker during final
  testing.
  5.  Each finished board will receive a
  MAC Address  sticker during final
  testing.
  6.  Install header shunt M1 (on J49) and
  M2 (on J50) during final testing.
- PCB LOGO:
  Texas Instruments
- PCB LOGO:
  WEEE and CE
- U1 Fiducials
- U3 Fiducials
- U37 Fiducials
- U45 Fiducials
- PCB LOGO:
  FCC disclaimer
- U21 Fiducials
- U24 Fiducials
- U9 Fiducials
- U13 Fiducials
- U15 Fiducials
- U17 Fiducials
- U5 Fiducials
- U6 Fiducials
- PCB LOGO:
  Caution Hot Surface
- U89 Fiducials
- U90 Fiducials
- U91 Fiducials
- PCB Top Fiducials
- PCB Bottom Fiducials
- Install label in silkscreened box after final wash.
- Text shall be 8 pt. Text shall be per the label table in the PDF schematics
- Variant / Label Table
- Variant
- Label Text
- 001
- TMDSIDK574
- 002
- TMDSIDK574H
